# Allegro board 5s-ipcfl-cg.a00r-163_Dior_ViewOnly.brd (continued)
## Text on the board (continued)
TOP: list("[Spacing] TOP" "9.Shape to Route Keepout" "0 MIL [DEFAULT]" "0 MIL" "0.00 MIL" "DRC ERROR CLASS/TOP" "[Shape] Route Keepout/All ((-3363.8 -570.56) (-3302.8 -509.56))" "[Top Shape] +3P3V_MSATA ((-3456.02 -996.0) (-3345.0 1131.0))" list(-3355.620000 -560.850000) nil)@@@list("eric2_tseng" "2019/01/23 17:32:01" nil "p143000044-pc" "5s-ipcfl-cg.a00r")@@@list("doris_chen" "2019/01/24 12:51:12" nil "p16c000356-pc" "5s-ipcfl-cg.a00r-chk") | list("[Physical] TOP" "97.Pad/Pad Direct Connect" "NOT_ALLOWED [100OHM(DP_4/8/5/200)]" "ALL_ALLOWED" "" "DRC ERROR CLASS/TOP" "[SmdPin] LAN_MDI3_P_C (<uTiL>cId3603<uTiL>.1) (-3209.34 2359.74)" "[SmdPin] LAN_MDI3_P_C (<uTiL>cId3097<uTiL>.2) (-3209.32 2358.76)" list(-3209.320000 2358.760000) nil)@@@list("eric2_tseng" "2019/01/23 17:33:15" nil "p143000044-pc" "5s-ipcfl-cg.a00r")@@@list("doris_chen" "2019/01/24 12:52:08" nil "p16c000356-pc" "5s-ipcfl-cg.a00r-chk") | list("[Physical] TOP" "139.Pad/Pad Direct Connect" "NOT_ALLOWED [100OHM(DP_4/8/5/200)]" "ALL_ALLOWED" "" "DRC ERROR CLASS/TOP" "[SmdPin] LAN_MDI3_P (<uTiL>cId3097<uTiL>.1) (-3209.32 2293.8)" "[SmdPin] LAN_MDI3_P (<uTiL>cId3603<uTiL>.2) (-3209.3 2292.82)" list(-3209.300000 2292.820000) nil)@@@list("eric2_tseng" "2019/01/23 17:34:18" nil "p143000044-pc" "5s-ipcfl-cg.a00r")@@@list("doris_chen" "2019/01/24 12:52:31" nil "p16c000356-pc" "5s-ipcfl-cg.a00r-chk") | list("[Physical] TOP" "96.Pad/Pad Direct Connect" "NOT_ALLOWED [100OHM(DP_4/8/5/200)]" "ALL_ALLOWED" "" "DRC ERROR CLASS/TOP" "[SmdPin] LAN_MDI3_N (<uTiL>cId3097<uTiL>.3) (-3177.82 2293.8)" "[SmdPin] LAN_MDI3_N (<uTiL>cId3603<uTiL>.3) (-3177.84 2292.82)" list(-3177.840000 2292.820000) nil)@@@list("eric2_tseng" "2019/01/23 17:34:27" nil "p143000044-pc" "5s-ipcfl-cg.a00r")@@@list("doris_chen" "2019/01/24 12:52:07" nil "p16c000356-pc" "5s-ipcfl-cg.a00r-chk") | list("[Physical] TOP" "74.Pad/Pad Direct Connect" "NOT_ALLOWED [100OHM(DP_4/8/5/200)]" "ALL_ALLOWED" "" "DRC ERROR CLASS/TOP" "[SmdPin] LAN_MDI3_N_C (<uTiL>cId3603<uTiL>.4) (-3177.84 2359.74)" "[SmdPin] LAN_MDI3_N_C (<uTiL>cId3097<uTiL>.4) (-3177.82 2358.76)" list(-3177.820000 2358.760000) nil)@@@list("eric2_tseng" "2019/01/23 17:33:40" nil "p143000044-pc" "5s-ipcfl-cg.a00r")@@@list("doris_chen" "2019/01/24 12:51:55" nil "p16c000356-pc" "5s-ipcfl-cg.a00r-chk") | list("[Physical] TOP" "192.Pad/Pad Direct Connect" "NOT_ALLOWED [100OHM(DP_4/8/5/200)]" "ALL_ALLOWED" "" "DRC ERROR CLASS/TOP" "[SmdPin] LAN_MDI2_P_C (<uTiL>cId3602<uTiL>.1) (-3121.34 2383.74)" "[SmdPin] LAN_MDI2_P_C (<uTiL>cId3096<uTiL>.2) (-3121.32 2382.76)" list(-3121.320000 2382.760000) nil)@@@list("eric2_tseng" "2019/01/23 17:33:52" nil "p143000044-pc" "5s-ipcfl-cg.a00r")@@@list("doris_chen" "2019/01/24 12:53:02" nil "p16c000356-pc" "5s-ipcfl-cg.a00r-chk") | list("[Physical] TOP" "191.Pad/Pad Direct Connect" "NOT_ALLOWED [100OHM(DP_4/8/5/200)]" "ALL_ALLOWED" "" "DRC ERROR CLASS/TOP" "[SmdPin] LAN_MDI2_P (<uTiL>cId3096<uTiL>.1) (-3121.32 2317.8)" "[SmdPin] LAN_MDI2_P (<uTiL>cId3602<uTiL>.2) (-3121.3 2316.82)" list(-3121.300000 2316.820000) nil)@@@list("eric2_tseng" "2019/01/23 17:33:17" nil "p143000044-pc" "5s-ipcfl-cg.a00r")@@@list("doris_chen" "2019/01/24 12:53:01" nil "p16c000356-pc" "5s-ipcfl-cg.a00r-chk") | list("[Physical] TOP" "75.Pad/Pad Direct Connect" "NOT_ALLOWED [100OHM(DP_4/8/5/200)]" "ALL_ALLOWED" "" "DRC ERROR CLASS/TOP" "[SmdPin] LAN_MDI2_N_C (<uTiL>cId3096<uTiL>.4) (-3089.82 2382.76)" "[SmdPin] LAN_MDI2_N_C (<uTiL>cId3602<uTiL>.4) (-3089.84 2383.74)" list(-3089.840000 2383.740000) nil)@@@list("eric2_tseng" "2019/01/23 17:33:46" nil "p143000044-pc" "5s-ipcfl-cg.a00r")@@@list("doris_chen" "2019/01/24 12:51:56" nil "p16c000356-pc" "5s-ipcfl-cg.a00r-chk") | list("[Physical] TOP" "104.Pad/Pad Direct Connect" "NOT_ALLOWED [100OHM(DP_4/8/5/200)]" "ALL_ALLOWED" "" "DRC ERROR CLASS/TOP" "[SmdPin] LAN_MDI2_N (<uTiL>cId3602<uTiL>.3) (-3089.84 2316.82)" "[SmdPin] LAN_MDI2_N (<uTiL>cId3096<uTiL>.3) (-3089.82 2317.8)" list(-3089.820000 2317.800000) nil)@@@list("eric2_tseng" "2019/01/23 17:33:16" nil "p143000044-pc" "5s-ipcfl-cg.a00r")@@@list("doris_chen" "2019/01/24 12:52:12" nil "p16c000356-pc" "5s-ipcfl-cg.a00r-chk") | list("[Physical] TOP" "141.Pad/Pad Direct Connect" "NOT_ALLOWED [100OHM(DP_4/8/5/200)]" "ALL_ALLOWED" "" "DRC ERROR CLASS/TOP" "[SmdPin] LAN_MDI1_P_C (<uTiL>cId3095<uTiL>.2) (-3033.32 2382.76)" "[SmdPin] LAN_MDI1_P_C (<uTiL>cId3601<uTiL>.1) (-3033.34 2383.74)" list(-3033.340000 2383.740000) nil)@@@list("eric2_tseng" "2019/01/23 17:34:15" nil "p143000044-pc" "5s-ipcfl-cg.a00r")@@@list("doris_chen" "2019/01/24 12:52:32" nil "p16c000356-pc" "5s-ipcfl-cg.a00r-chk") | list("[Physical] TOP" "140.Pad/Pad Direct Connect" "NOT_ALLOWED [100OHM(DP_4/8/5/200)]" "ALL_ALLOWED" "" "DRC ERROR CLASS/TOP" "[SmdPin] LAN_MDI1_P (<uTiL>cId3095<uTiL>.1) (-3033.32 2317.8)" "[SmdPin] LAN_MDI1_P (<uTiL>cId3601<uTiL>.2) (-3033.3 2316.82)" list(-3033.300000 2316.820000) nil)@@@list("eric2_tseng" "2019/01/23 17:33:57" nil "p143000044-pc" "5s-ipcfl-cg.a00r")@@@list("doris_chen" "2019/01/24 12:52:31" nil "p16c000356-pc" "5s-ipcfl-cg.a00r-chk") | list("[Physical] TOP" "99.Pad/Pad Direct Connect" "NOT_ALLOWED [100OHM(DP_4/8/5/200)]" "ALL_ALLOWED" "" "DRC ERROR CLASS/TOP" "[SmdPin] LAN_MDI1_N_C (<uTiL>cId3095<uTiL>.4) (-3001.82 2382.76)" "[SmdPin] LAN_MDI1_N_C (<uTiL>cId3601<uTiL>.4) (-3001.84 2383.74)" list(-3001.840000 2383.740000) nil)@@@list("eric2_tseng" "2019/01/23 17:34:14" nil "p143000044-pc" "5s-ipcfl-cg.a00r")@@@list("doris_chen" "2019/01/24 12:52:09" nil "p16c000356-pc" "5s-ipcfl-cg.a00r-chk") | list("[Physical] TOP" "98.Pad/Pad Direct Connect" "NOT_ALLOWED [100OHM(DP_4/8/5/200)]" "ALL_ALLOWED" "" "DRC ERROR CLASS/TOP" "[SmdPin] LAN_MDI1_N (<uTiL>cId3095<uTiL>.3) (-3001.82 2317.8)" "[SmdPin] LAN_MDI1_N (<uTiL>cId3601<uTiL>.3) (-3001.84 2316.82)" list(-3001.840000 2316.820000) nil)@@@list("eric2_tseng" "2019/01/23 17:33:16" nil "p143000044-pc" "5s-ipcfl-cg.a00r")@@@list("doris_chen" "2019/01/24 12:52:08" nil "p16c000356-pc" "5s-ipcfl-cg.a00r-chk") | list("[Physical] TOP" "45.Pad/Pad Direct Connect" "NOT_ALLOWED [100OHM(DP_4/8/5/200)]" "ALL_ALLOWED" "" "DRC ERROR CLASS/TOP" "[SmdPin] LAN_MDI0_P_C (<uTiL>cId3600<uTiL>.1) (-2944.34 2383.74)" "[SmdPin] LAN_MDI0_P_C (<uTiL>cId3094<uTiL>.2) (-2944.32 2382.76)" list(-2944.320000 2382.760000) nil)@@@list("eric2_tseng" "2019/01/23 17:33:46" nil "p143000044-pc" "5s-ipcfl-cg.a00r")@@@list("doris_chen" "2019/01/24 12:51:36" nil "p16c000356-pc" "5s-ipcfl-cg.a00r-chk") | list("[Physical] TOP" "193.Pad/Pad Direct Connect" "NOT_ALLOWED [100OHM(DP_4/8/5/200)]" "ALL_ALLOWED" "" "DRC ERROR CLASS/TOP" "[SmdPin] LAN_MDI0_P (<uTiL>cId3600<uTiL>.2) (-2944.3 2316.82)" "[SmdPin] LAN_MDI0_P (<uTiL>cId3094<uTiL>.1) (-2944.32 2317.8)" list(-2944.320000 2317.800000) nil)@@@list("eric2_tseng" "2019/01/23 17:33:17" nil "p143000044-pc" "5s-ipcfl-cg.a00r")@@@list("doris_chen" "2019/01/24 12:53:02" nil "p16c000356-pc" "5s-ipcfl-cg.a00r-chk") | list("[Physical] TOP" "86.Pad/Pad Direct Connect" "NOT_ALLOWED [100OHM(DP_4/8/5/200)]" "ALL_ALLOWED" "" "DRC ERROR CLASS/TOP" "[SmdPin] LAN_MDI0_N_C (<uTiL>cId3094<uTiL>.4) (-2912.82 2382.76)" "[SmdPin] LAN_MDI0_N_C (<uTiL>cId3600<uTiL>.4) (-2912.84 2383.74)" list(-2912.840000 2383.740000) nil)@@@list("eric2_tseng" "2019/01/23 17:33:58" nil "p143000044-pc" "5s-ipcfl-cg.a00r")@@@list("doris_chen" "2019/01/24 12:52:02" nil "p16c000356-pc" "5s-ipcfl-cg.a00r-chk") | list("[Physical] TOP" "76.Pad/Pad Direct Connect" "NOT_ALLOWED [100OHM(DP_4/8/5/200)]" "ALL_ALLOWED" "" "DRC ERROR CLASS/TOP" "[SmdPin] LAN_MDI0_N (<uTiL>cId3600<uTiL>.3) (-2912.84 2316.82)" "[SmdPin] LAN_MDI0_N (<uTiL>cId3094<uTiL>.3) (-2912.82 2317.8)" list(-2912.820000 2317.800000) nil)@@@list("eric2_tseng" "2019/01/23 17:34:28" nil "p143000044-pc" "5s-ipcfl-cg.a00r")@@@list("doris_chen" "2019/01/24 12:51:56" nil "p16c000356-pc" "5s-ipcfl-cg.a00r-chk") | list("[Physical] TOP" "169.Pad/Pad Direct Connect" "NOT_ALLOWED [(GND_20)]" "ALL_ALLOWED" "" "DRC ERROR CLASS/TOP" "[ThruPin] GND (<uTiL>cId2106<uTiL>.52) (-2879.07 -1710.4)" "[SmdPin] GND (<uTiL>cId2106<uTiL>.49) (-2799.57 -1789.9)" list(-2879.070000 -1710.400000) nil)@@@list("eric2_tseng" "2019/01/23 17:33:20" nil "p143000044-pc" "5s-ipcfl-cg.a00r")@@@list("doris_chen" "2019/01/24 12:52:50" nil "p16c000356-pc" "5s-ipcfl-cg.a00r-chk") | list("[Physical] TOP" "170.Pad/Pad Direct Connect" "NOT_ALLOWED [(GND_20)]" "ALL_ALLOWED" "" "DRC ERROR CLASS/TOP" "[ThruPin] GND (<uTiL>cId2106<uTiL>.54) (-2879.07 -1789.9)" "[SmdPin] GND (<uTiL>cId2106<uTiL>.49) (-2799.57 -1789.9)" list(-2879.070000 -1789.900000) nil)@@@list("eric2_tseng" "2019/01/23 17:34:10" nil "p143000044-pc" "5s-ipcfl-cg.a00r")@@@list("doris_chen" "2019/01/24 12:52:50" nil "p16c000356-pc" "5s-ipcfl-cg.a00r-chk") | list("[Physical] TOP" "172.Pad/Pad Direct Connect" "NOT_ALLOWED [(GND_20)]" "ALL_ALLOWED" "" "DRC ERROR CLASS/TOP" "[ThruPin] GND (<uTiL>cId2106<uTiL>.57) (-2879.07 -1869.4)" "[SmdPin] GND (<uTiL>cId2106<uTiL>.49) (-2799.57 -1789.9)" list(-2879.070000 -1869.400000) nil)@@@list("eric2_tseng" "2019/01/23 17:33:59" nil "p143000044-pc" "5s-ipcfl-cg.a00r")@@@list("doris_chen" "2019/01/24 12:52:51" nil "p16c000356-pc" "5s-ipcfl-cg.a00r-chk") | list("[Physical] TOP" "168.Pad/Pad Direct Connect" "NOT_ALLOWED [(GND_20)]" "ALL_ALLOWED" "" "DRC ERROR CLASS/TOP" "[ThruPin] GND (<uTiL>cId2106<uTiL>.51) (-2799.57 -1710.4)" "[SmdPin] GND (<uTiL>cId2106<uTiL>.49) (-2799.57 -1789.9)" list(-2799.570000 -1710.400000) nil)@@@list("eric2_tseng" "2019/01/23 17:33:21" nil "p143000044-pc" "5s-ipcfl-cg.a00r")@@@list("doris_chen" "2019/01/24 12:52:49" nil "p16c000356-pc" "5s-ipcfl-cg.a00r-chk") | list("[Physical] TOP" "173.Pad/Pad Direct Connect" "NOT_ALLOWED [(GND_20)]" "ALL_ALLOWED" "" "DRC ERROR CLASS/TOP" "[ThruPin] GND (<uTiL>cId2106<uTiL>.58) (-2799.57 -1789.9)" "[SmdPin] GND (<uTiL>cId2106<uTiL>.49) (-2799.57 -1789.9)" list(-2799.570000 -1789.900000) nil)@@@list("eric2_tseng" "2019/01/23 17:33:19" nil "p143000044-pc" "5s-ipcfl-cg.a00r")@@@list("doris_chen" "2019/01/24 12:52:52" nil "p16c000356-pc" "5s-ipcfl-cg.a00r-chk") | list("[Physical] TOP" "171.Pad/Pad Direct Connect" "NOT_ALLOWED [(GND_20)]" "ALL_ALLOWED" "" "DRC ERROR CLASS/TOP" "[ThruPin] GND (<uTiL>cId2106<uTiL>.56) (-2799.57 -1869.4)" "[SmdPin] GND (<uTiL>cId2106<uTiL>.49) (-2799.57 -1789.9)" list(-2799.570000 -1869.400000) nil)@@@list("eric2_tseng" "2019/01/23 17:33:20" nil "p143000044-pc" "5s-ipcfl-cg.a00r")@@@list("doris_chen" "2019/01/24 12:52:51" nil "p16c000356-pc" "5s-ipcfl-cg.a00r-chk") | list("[Spacing] TOP" "14.Shape to Route Keepin" "0 MIL [DEFAULT]" "0 MIL" "0.00 MIL" "DRC ERROR CLASS/TOP" "[Shape] Route Keepin/All ((-3483.94 -2629.6) (3168.97 4113.86))" "[Top Shape] GND ((-2728.18 -2401.25) (-2614.45 -2216.13))" list(-2728.030000 -2224.450000) nil)@@@list("eric2_tseng" "2019/01/23 17:32:01" nil "p143000044-pc" "5s-ipcfl-cg.a00r")@@@list("doris_chen" "2019/01/24 12:51:15" nil "p16c000356-pc" "5s-ipcfl-cg.a00r-chk") | list("[Physical] TOP" "166.Pad/Pad Direct Connect" "NOT_ALLOWED [(GND_20)]" "ALL_ALLOWED" "" "DRC ERROR CLASS/TOP" "[ThruPin] GND (<uTiL>cId2106<uTiL>.50) (-2720.07 -1710.4)" "[SmdPin] GND (<uTiL>cId2106<uTiL>.49) (-2799.57 -1789.9)" list(-2720.070000 -1710.400000) nil)@@@list("eric2_tseng" "2019/01/23 17:33:21" nil "p143000044-pc" "5s-ipcfl-cg.a00r")@@@list("doris_chen" "2019/01/24 12:52:48" nil "p16c000356-pc" "5s-ipcfl-cg.a00r-chk") | list("[Physical] TOP" "174.Pad/Pad Direct Connect" "NOT_ALLOWED [(GND_20)]" "ALL_ALLOWED" "" "DRC ERROR CLASS/TOP" "[SmdPin] GND (<uTiL>cId2106<uTiL>.49) (-2799.57 -1789.9)" "[ThruPin] GND (<uTiL>cId2106<uTiL>.53) (-2720.07 -1789.9)" list(-2720.070000 -1789.900000) nil)@@@list("eric2_tseng" "2019/01/23 17:33:42" nil "p143000044-pc" "5s-ipcfl-cg.a00r")@@@list("doris_chen" "2019/01/24 12:52:52" nil "p16c000356-pc" "5s-ipcfl-cg.a00r-chk") | list("[Physical] TOP" "167.Pad/Pad Direct Connect" "NOT_ALLOWED [(GND_20)]" "ALL_ALLOWED" "" "DRC ERROR CLASS/TOP" "[ThruPin] GND (<uTiL>cId2106<uTiL>.55) (-2720.07 -1869.4)" "[SmdPin] GND (<uTiL>cId2106<uTiL>.49) (-2799.57 -1789.9)" list(-2720.070000 -1869.400000) nil)@@@list("eric2_tseng" "2019/01/23 17:34:21" nil "p143000044-pc" "5s-ipcfl-cg.a00r")@@@list("doris_chen" "2019/01/24 12:52:49" nil "p16c000356-pc" "5s-ipcfl-cg.a00r-chk") | list("[Physical] TOP" "161.Pad/Pad Direct Connect" "NOT_ALLOWED [(PWR_20)]" "ALL_ALLOWED" "" "DRC ERROR CLASS/TOP" "[SmdPin] +VCCSA_VIN (<uTiL>cId5471<uTiL>.1) (-2412.4 1987.1)" "[SmdPin] +VCCSA_VIN (<uTiL>cId5435<uTiL>.2) (-2412.0 2000.5)" list(-2412.000000 2000.500000) nil)@@@list("eric2_tseng" "2019/01/23 17:34:21" nil "p143000044-pc" "5s-ipcfl-cg.a00r")@@@list("doris_chen" "2019/01/24 12:52:45" nil "p16c000356-pc" "5s-ipcfl-cg.a00r-chk") | list("[Spacing] TOP" "1.Shape to Route Keepin" "0 MIL [DEFAULT]" "0 MIL" "0.00 MIL" "DRC ERROR CLASS/TOP" "[Shape] Route Keepin/All ((-3483.94 -2629.6) (3168.97 4113.86))" "[Top Shape] GND_AUDIO ((-2594.47 -2629.61) (-2177.88 -2145.28))" list(-2379.690000 -2629.600000) nil)@@@list("eric2_tseng" "2019/01/23 17:31:58" nil "p143000044-pc" "5s-ipcfl-cg.a00r")@@@list("doris_chen" "2019/01/24 12:51:08" nil "p16c000356-pc" "5s-ipcfl-cg.a00r-chk") | list("[Physical] TOP" "91.Pad/Pad Direct Connect" "NOT_ALLOWED [85OHM(DP_5|5/5|5.5/5/200)]" "ALL_ALLOWED" "" "DRC ERROR CLASS/TOP" "[SmdPin] USB_PP14_M.2_BT_R (<uTiL>cId3099<uTiL>.2) (-2302.18 -421.8)" "[SmdPin] USB_PP14_M.2_BT_R (<uTiL>cId3180<uTiL>.3) (-2302.18 -417.86)" list(-2302.180000 -417.860000) nil)@@@list("eric2_tseng" "2019/01/23 17:33:44" nil "p143000044-pc" "5s-ipcfl-cg.a00r")@@@list("doris_chen" "2019/01/24 12:52:05" nil "p16c000356-pc" "5s-ipcfl-cg.a00r-chk") | list("[Physical] TOP" "135.Pad/Pad Direct Connect" "NOT_ALLOWED [85OHM(DP_5|5/5|5.5/5/200)]" "ALL_ALLOWED" "" "DRC ERROR CLASS/TOP" "[SmdPin] USB_PP14_M.2_BT (<uTiL>cId3180<uTiL>.4) (-2302.18 -490.7)" "[SmdPin] USB_PP14_M.2_BT (<uTiL>cId3099<uTiL>.1) (-2302.18 -486.76)" list(-2302.180000 -486.760000) nil)@@@list("eric2_tseng" "2019/01/23 17:34:25" nil "p143000044-pc" "5s-ipcfl-cg.a00r")@@@list("doris_chen" "2019/01/24 12:52:28" nil "p16c000356-pc" "5s-ipcfl-cg.a00r-chk") | list("[Physical] TOP" "190.Pad/Pad Direct Connect" "NOT_ALLOWED [85OHM(DP_5|5/5|5.5/5/200)]" "ALL_ALLOWED" "" "DRC ERROR CLASS/TOP" "[SmdPin] USB_PN14_M.2_BT_R (<uTiL>cId3180<uTiL>.2) (-2270.68 -417.86)" "[SmdPin] USB_PN14_M.2_BT_R (<uTiL>cId3099<uTiL>.4) (-2270.68 -421.8)" list(-2270.680000 -421.800000) nil)@@@list("eric2_tseng" "2019/01/23 17:34:20" nil "p143000044-pc" "5s-ipcfl-cg.a00r")@@@list("doris_chen" "2019/01/24 12:53:01" nil "p16c000356-pc" "5s-ipcfl-cg.a00r-chk") | list("[Physical] TOP" "103.Pad/Pad Direct Connect" "NOT_ALLOWED [85OHM(DP_5|5/5|5.5/5/200)]" "ALL_ALLOWED" "" "DRC ERROR CLASS/TOP" "[SmdPin] USB_PN14_M.2_BT (<uTiL>cId3180<uTiL>.1) (-2270.68 -490.7)" "[SmdPin] USB_PN14_M.2_BT (<uTiL>cId3099<uTiL>.3) (-2270.68 -486.76)" list(-2270.680000 -486.760000) nil)@@@list("eric2_tseng" "2019/01/23 17:33:11" nil "p143000044-pc" "5s-ipcfl-cg.a00r")@@@list("doris_chen" "2019/01/24 12:52:11" nil "p16c000356-pc" "5s-ipcfl-cg.a00r-chk") | list("[Physical] TOP" "142.Pad/Pad Direct Connect" "NOT_ALLOWED [DEFAULT]" "ALL_ALLOWED" "" "DRC ERROR CLASS/TOP" "[ThruPin] PCH_HEATSINK_DET (<uTiL>cId6011<uTiL>.4) (-2152.51 -10.63)" "[ThruPin] PCH_HEATSINK_DET (<uTiL>cId5725<uTiL>.1) (-2152.52 -10.63)" list(-2152.520000 -10.630000) nil)@@@list("eric2_tseng" "2019/01/23 17:34:16" nil "p143000044-pc" "5s-ipcfl-cg.a00r")@@@list("doris_chen" "2019/01/24 12:52:32" nil "p16c000356-pc" "5s-ipcfl-cg.a00r-chk") | list("[Spacing-SameNet] TOP" "36.Line to Line Same Net" "4 MIL [DEFAULT]" "0 MIL" "4.00 MIL" "DRC ERROR CLASS/TOP" "[Line] PCH_HEATSINK_DET ((-2154.52 -68.02) (-2150.52 -8.63))" "[Line] PCH_HEATSINK_DET ((-2154.51 -12.63) (-2150.51 -8.62))" list(-2152.520000 -10.630000) nil)@@@list("eric2_tseng" "2019/01/23 17:32:53" nil "p143000044-pc" "5s-ipcfl-cg.a00r")@@@list("doris_chen" "2019/01/24 12:51:32" nil "p16c000356-pc" "5s-ipcfl-cg.a00r-chk") | list("[Physical] TOP" "109.Pad/Pad Direct Connect" "NOT_ALLOWED [DEFAULT]" "ALL_ALLOWED" "" "DRC ERROR CLASS/TOP" "[ThruPin] PCH_HEATSINK_DET (<uTiL>cId5725<uTiL>.2) (-2152.52 189.37)" "[ThruPin] PCH_HEATSINK_DET (<uTiL>cId6011<uTiL>.3) (-2152.51 189.37)" list(-2152.510000 189.370000) nil)@@@list("eric2_tseng" "2019/01/23 17:34:16" nil "p143000044-pc" "5s-ipcfl-cg.a00r")@@@list("doris_chen" "2019/01/24 12:52:14" nil "p16c000356-pc" "5s-ipcfl-cg.a00r-chk") | list("[Physical] TOP" "159.Pad/Pad Direct Connect" "NOT_ALLOWED [85OHM(DP_5|5/5|5.5/5/200)]" "ALL_ALLOWED" "" "DRC ERROR CLASS/TOP" "[SmdPin] USB_PP7_B3_R (<uTiL>cId698<uTiL>.4) (-1911.55 3427.18)" "[SmdPin] USB_PP7_B3_R (<uTiL>cId634<uTiL>.2) (-1913.52 3425.21)" list(-1913.520000 3425.210000) nil)@@@list("eric2_tseng" "2019/01/23 17:33:44" nil "p143000044-pc" "5s-ipcfl-cg.a00r")@@@list("doris_chen" "2019/01/24 12:52:44" nil "p16c000356-pc" "5s-ipcfl-cg.a00r-chk") | list("[Physical] TOP" "72.Pad/Pad Direct Connect" "NOT_ALLOWED [85OHM(DP_5|5/5|5.5/5/200)]" "ALL_ALLOWED" "" "DRC ERROR CLASS/TOP" "[SmdPin] USB_PP7_B3 (<uTiL>cId634<uTiL>.1) (-1913.52 3379.93)" "[SmdPin] USB_PP7_B3 (<uTiL>cId698<uTiL>.1) (-1911.55 3377.96)" list(-1911.550000 3377.960000) nil)@@@list("eric2_tseng" "2019/01/23 17:34:24" nil "p143000044-pc" "5s-ipcfl-cg.a00r")@@@list("doris_chen" "2019/01/24 12:51:54" nil "p16c000356-pc" "5s-ipcfl-cg.a00r-chk") | list("[Physical] TOP" "59.Pad/Pad Direct Connect" "NOT_ALLOWED [85OHM(DP_5|5/5|5.5/5/200)]" "ALL_ALLOWED" "" "DRC ERROR CLASS/TOP" "[SmdPin] USB_PN7_B3_R (<uTiL>cId634<uTiL>.4) (-1887.92 3425.21)" "[SmdPin] USB_PN7_B3_R (<uTiL>cId698<uTiL>.3) (-1889.89 3427.18)" list(-1889.890000 3427.180000) nil)@@@list("eric2_tseng" "2019/01/23 17:33:41" nil "p143000044-pc" "5s-ipcfl-cg.a00r")@@@list("doris_chen" "2019/01/24 12:51:44" nil "p16c000356-pc" "5s-ipcfl-cg.a00r-chk") | list("[Physical] TOP" "188.Pad/Pad Direct Connect" "NOT_ALLOWED [85OHM(DP_5|5/5|5.5/5/200)]" "ALL_ALLOWED" "" "DRC ERROR CLASS/TOP" "[SmdPin] USB_PN7_B3 (<uTiL>cId634<uTiL>.3) (-1887.92 3379.93)" "[SmdPin] USB_PN7_B3 (<uTiL>cId698<uTiL>.2) (-1889.89 3377.96)" list(-1889.890000 3377.960000) nil)@@@list("eric2_tseng" "2019/01/23 17:33:09" nil "p143000044-pc" "5s-ipcfl-cg.a00r")@@@list("doris_chen" "2019/01/24 12:53:00" nil "p16c000356-pc" "5s-ipcfl-cg.a00r-chk") | list("[Physical] TOP" "120.Pad/Pad Direct Connect" "NOT_ALLOWED [85OHM(DP_5|5/5|5.5/5/200)]" "ALL_ALLOWED" "" "DRC ERROR CLASS/TOP" "[SmdPin] USB_PP8_B4 (<uTiL>cId697<uTiL>.1) (-1851.55 3377.96)" "[SmdPin] USB_PP8_B4 (<uTiL>cId631<uTiL>.1) (-1853.52 3379.93)" list(-1853.520000 3379.930000) nil)@@@list("eric2_tseng" "2019/01/23 17:33:13" nil "p143000044-pc" "5s-ipcfl-cg.a00r")@@@list("doris_chen" "2019/01/24 12:52:21" nil "p16c000356-pc" "5s-ipcfl-cg.a00r-chk") | list("[Physical] TOP" "187.Pad/Pad Direct Connect" "NOT_ALLOWED [85OHM(DP_5|5/5|5.5/5/200)]" "ALL_ALLOWED" "" "DRC ERROR CLASS/TOP" "[SmdPin] USB_PP8_B4_R (<uTiL>cId631<uTiL>.2) (-1853.52 3425.21)" "[SmdPin] USB_PP8_B4_R (<uTiL>cId697<uTiL>.4) (-1851.55 3427.18)" list(-1851.550000 3427.180000) nil)@@@list("eric2_tseng" "2019/01/23 17:34:24" nil "p143000044-pc" "5s-ipcfl-cg.a00r")@@@list("doris_chen" "2019/01/24 12:52:59" nil "p16c000356-pc" "5s-ipcfl-cg.a00r-chk") | list("[Physical] TOP" "94.Pad/Pad Direct Connect" "NOT_ALLOWED [85OHM(DP_5|5/5|5.5/5/200)]" "ALL_ALLOWED" "" "DRC ERROR CLASS/TOP" "[SmdPin] USB_PN8_B4_R (<uTiL>cId631<uTiL>.4) (-1827.92 3425.21)" "[SmdPin] USB_PN8_B4_R (<uTiL>cId697<uTiL>.3) (-1829.89 3427.18)" list(-1829.890000 3427.180000) nil)@@@list("eric2_tseng" "2019/01/23 17:34:23" nil "p143000044-pc" "5s-ipcfl-cg.a00r")@@@list("doris_chen" "2019/01/24 12:52:06" nil "p16c000356-pc" "5s-ipcfl-cg.a00r-chk") | list("[Physical] TOP" "87.Pad/Pad Direct Connect" "NOT_ALLOWED [85OHM(DP_5|5/5|5.5/5/200)]" "ALL_ALLOWED" "" "DRC ERROR CLASS/TOP" "[SmdPin] USB_PN8_B4 (<uTiL>cId697<uTiL>.2) (-1829.89 3377.96)" "[SmdPin] USB_PN8_B4 (<uTiL>cId631<uTiL>.3) (-1827.92 3379.93)" list(-1827.920000 3379.930000) nil)@@@list("eric2_tseng" "2019/01/23 17:33:11" nil "p143000044-pc" "5s-ipcfl-cg.a00r")@@@list("doris_chen" "2019/01/24 12:52:02" nil "p16c000356-pc" "5s-ipcfl-cg.a00r-chk") | list("[Spacing] TOP" "12.Shape to Route Keepin" "0 MIL [DEFAULT]" "0 MIL" "0.00 MIL" "DRC ERROR CLASS/TOP" "[Shape] Route Keepin/All ((-3483.94 -2629.6) (3168.97 4113.86))" "[Top Shape] GND_AUDIO ((-2170.95 -2629.61) (-1679.58 -2154.72))" list(-1679.580000 -2629.600000) nil)@@@list("eric2_tseng" "2019/01/23 17:32:00" nil "p143000044-pc" "5s-ipcfl-cg.a00r")@@@list("doris_chen" "2019/01/24 12:51:14" nil "p16c000356-pc" "5s-ipcfl-cg.a00r-chk") | list("[Spacing] TOP" "13.Shape to Route Keepin" "0 MIL [DEFAULT]" "0 MIL" "0.00 MIL" "DRC ERROR CLASS/TOP" "[Shape] Route Keepin/All ((-3483.94 -2629.6) (3168.97 4113.86))" "[Top Shape] GND ((-1658.98 -2629.61) (-868.57 -2250.87))" list(-1658.980000 -2629.600000) nil)@@@list("eric2_tseng" "2019/01/23 17:31:59" nil "p143000044-pc" "5s-ipcfl-cg.a00r")@@@list("doris_chen" "2019/01/24 12:51:14" nil "p16c000356-pc" "5s-ipcfl-cg.a00r-chk") | list("[Physical] TOP" "65.Pad/Pad Direct Connect" "NOT_ALLOWED [(GND_20)]" "ALL_ALLOWED" "" "DRC ERROR CLASS/TOP" "[SmdPin] GND (<uTiL>cId5666<uTiL>.17) (-1505.0 2702.0)" "[ThruPin] GND (<uTiL>cId5666<uTiL>.18) (-1526.0 2723.0)" list(-1526.000000 2723.000000) nil)@@@list("eric2_tseng" "2019/01/23 17:33:22" nil "p143000044-pc" "5s-ipcfl-cg.a00r")@@@list("doris_chen" "2019/01/24 12:51:50" nil "p16c000356-pc" "5s-ipcfl-cg.a00r-chk") | list("[Spacing] TOP" "7.SMD Pin to SMD Pin" "5 MIL [DEFAULT]" "OVERLAP" "" "DRC ERROR CLASS/TOP" "[SmdPin] Dummy (<uTiL>cId5785<uTiL>.3) (-1471.26 213.0)" "[SmdPin] Dummy (<uTiL>cId4553<uTiL>.3) (-1470.98 213.0)" list(-1500.480000 203.000000) nil)@@@list("eric2_tseng" "2019/01/23 17:31:57" nil "p143000044-pc" "5s-ipcfl-cg.a00r")@@@list("doris_chen" "2019/01/24 12:51:11" nil "p16c000356-pc" "5s-ipcfl-cg.a00r-chk") | list("[Spacing] TOP" "11.SMD Pin to SMD Pin" "5 MIL [DEFAULT]" "OVERLAP" "" "DRC ERROR CLASS/TOP" "[SmdPin] Dummy (<uTiL>cId5785<uTiL>.4) (-1471.26 163.0)" "[SmdPin] Dummy (<uTiL>cId4553<uTiL>.4) (-1470.98 163.0)" list(-1500.480000 153.000000) nil)@@@list("eric2_tseng" "2019/01/23 17:31:58" nil "p143000044-pc" "5s-ipcfl-cg.a00r")@@@list("doris_chen" "2019/01/24 12:51:13" nil "p16c000356-pc" "5s-ipcfl-cg.a00r-chk") | list("[Spacing] TOP" "4.SMD Pin to SMD Pin" "5 MIL [DEFAULT]" "OVERLAP" "" "DRC ERROR CLASS/TOP" "[SmdPin] Dummy (<uTiL>cId5785<uTiL>.5) (-1471.26 113.0)" "[SmdPin] Dummy (<uTiL>cId4553<uTiL>.5) (-1470.98 113.0)" list(-1500.480000 103.000000) nil)@@@list("eric2_tseng" "2019/01/23 17:32:00" nil "p143000044-pc" "5s-ipcfl-cg.a00r")@@@list("doris_chen" "2019/01/24 12:51:10" nil "p16c000356-pc" "5s-ipcfl-cg.a00r-chk") | list("[Spacing] TOP" "15.SMD Pin to SMD Pin" "5 MIL [DEFAULT]" "OVERLAP" "" "DRC ERROR CLASS/TOP" "[SmdPin] Dummy (<uTiL>cId5785<uTiL>.6) (-1471.26 63.0)" "[SmdPin] Dummy (<uTiL>cId4553<uTiL>.6) (-1470.98 63.0)" list(-1500.480000 53.000000) nil)@@@list("eric2_tseng" "2019/01/23 17:31:58" nil "p143000044-pc" "5s-ipcfl-cg.a00r")@@@list("doris_chen" "2019/01/24 12:51:15" nil "p16c000356-pc" "5s-ipcfl-cg.a00r-chk") | list("[Physical] TOP" "164.Pad/Pad Direct Connect" "NOT_ALLOWED [(GND_20)]" "ALL_ALLOWED" "" "DRC ERROR CLASS/TOP" "[SmdPin] GND (<uTiL>cId5666<uTiL>.17) (-1505.0 2702.0)" "[ThruPin] GND (<uTiL>cId5666<uTiL>.19) (-1484.0 2681.0)" list(-1484.000000 2681.000000) nil)@@@list("eric2_tseng" "2019/01/23 17:34:10" nil "p143000044-pc" "5s-ipcfl-cg.a00r")@@@list("doris_chen" "2019/01/24 12:52:47" nil "p16c000356-pc" "5s-ipcfl-cg.a00r-chk") | list("[Physical] TOP" "95.Pad/Pad Direct Connect" "NOT_ALLOWED [50OHM(5)]" "ALL_ALLOWED" "" "DRC ERROR CLASS/TOP" "[SmdPin] R_SPI_IO3_R (<uTiL>cId5785<uTiL>.1) (-1471.26 313.0)" "[SmdPin] R_SPI_IO3_R (<uTiL>cId4553<uTiL>.1) (-1470.98 313.0)" list(-1470.980000 313.000000) nil)@@@list("eric2_tseng" "2019/01/23 17:33:45" nil "p143000044-pc" "5s-ipcfl-cg.a00r")@@@list("doris_chen" "2019/01/24 12:52:07" nil "p16c000356-pc" "5s-ipcfl-cg.a00r-chk") | list("[Physical] TOP" "100.Pad/Pad Direct Connect" "NOT_ALLOWED [(PWR_20)]" "ALL_ALLOWED" "" "DRC ERROR CLASS/TOP" "[SmdPin] +3P3VSB (<uTiL>cId5785<uTiL>.2) (-1471.26 263.0)" "[SmdPin] +3P3VSB (<uTiL>cId4553<uTiL>.2) (-1470.98 263.0)" list(-1470.980000 263.000000) nil)@@@list("eric2_tseng" "2019/01/23 17:33:28" nil "p143000044-pc" "5s-ipcfl-cg.a00r")@@@list("doris_chen" "2019/01/24 12:52:09" nil "p16c000356-pc" "5s-ipcfl-cg.a00r-chk") | list("[Physical] TOP" "110.Pad/Pad Direct Connect" "NOT_ALLOWED [50OHM(5)]" "ALL_ALLOWED" "" "DRC ERROR CLASS/TOP" "[SmdPin] R_SPI_CS0#_E56 (<uTiL>cId5785<uTiL>.7) (-1471.26 13.0)" "[SmdPin] R_SPI_CS0#_E56 (<uTiL>cId4553<uTiL>.7) (-1470.98 13.0)" list(-1470.980000 13.000000) nil)@@@list("eric2_tseng" "2019/01/23 17:33:12" nil "p143000044-pc" "5s-ipcfl-cg.a00r")@@@list("doris_chen" "2019/01/24 12:52:15" nil "p16c000356-pc" "5s-ipcfl-cg.a00r-chk") | list("[Physical] TOP" "189.Pad/Pad Direct Connect" "NOT_ALLOWED [50OHM(5)]" "ALL_ALLOWED" "" "DRC ERROR CLASS/TOP" "[SmdPin] R_SPI_IO1 (<uTiL>cId5785<uTiL>.8) (-1471.26 -37.0)" "[SmdPin] R_SPI_IO1 (<uTiL>cId4553<uTiL>.8) (-1470.98 -37.0)" list(-1470.980000 -37.000000) nil)@@@list("eric2_tseng" "2019/01/23 17:34:07" nil "p143000044-pc" "5s-ipcfl-cg.a00r")@@@list("doris_chen" "2019/01/24 12:53:00" nil "p16c000356-pc" "5s-ipcfl-cg.a00r-chk") | list("[Physical] TOP" "176.Pad/Pad Direct Connect" "NOT_ALLOWED [(PWR_20)]" "ALL_ALLOWED" "" "DRC ERROR CLASS/TOP" "[SmdPin] +VCCSA (<uTiL>cId5433<uTiL>.1) (-1242.99 1900.49)" "[SmdPin] +VCCSA (<uTiL>cId5656<uTiL>.1) (-1243.7 1841.92)" list(-1242.990000 1900.490000) nil)@@@list("eric2_tseng" "2019/01/23 17:34:11" nil "p143000044-pc" "5s-ipcfl-cg.a00r")@@@list("doris_chen" "2019/01/24 12:52:53" nil "p16c000356-pc" "5s-ipcfl-cg.a00r-chk") | list("[Spacing] TOP" "6.SMD Pin to SMD Pin" "5 MIL [DEFAULT]" "OVERLAP" "" "DRC ERROR CLASS/TOP" "[SmdPin] Dummy (<uTiL>cId5785<uTiL>.14) (-1092.74 213.0)" "[SmdPin] Dummy (<uTiL>cId4553<uTiL>.14) (-1093.02 213.0)" list(-1122.520000 203.000000) nil)@@@list("eric2_tseng" "2019/01/23 17:31:57" nil "p143000044-pc" "5s-ipcfl-cg.a00r")@@@list("doris_chen" "2019/01/24 12:51:11" nil "p16c000356-pc" "5s-ipcfl-cg.a00r-chk") | list("[Spacing] TOP" "3.SMD Pin to SMD Pin" "5 MIL [DEFAULT]" "OVERLAP" "" "DRC ERROR CLASS/TOP" "[SmdPin] Dummy (<uTiL>cId5785<uTiL>.13) (-1092.74 163.0)" "[SmdPin] Dummy (<uTiL>cId4553<uTiL>.13) (-1093.02 163.0)" list(-1122.520000 153.000000) nil)@@@list("eric2_tseng" "2019/01/23 17:31:56" nil "p143000044-pc" "5s-ipcfl-cg.a00r")@@@list("doris_chen" "2019/01/24 12:51:09" nil "p16c000356-pc" "5s-ipcfl-cg.a00r-chk") | list("[Spacing] TOP" "5.SMD Pin to SMD Pin" "5 MIL [DEFAULT]" "OVERLAP" "" "DRC ERROR CLASS/TOP" "[SmdPin] Dummy (<uTiL>cId5785<uTiL>.12) (-1092.74 113.0)" "[SmdPin] Dummy (<uTiL>cId4553<uTiL>.12) (-1093.02 113.0)" list(-1122.520000 103.000000) nil)@@@list("eric2_tseng" "2019/01/23 17:31:56" nil "p143000044-pc" "5s-ipcfl-cg.a00r")@@@list("doris_chen" "2019/01/24 12:51:10" nil "p16c000356-pc" "5s-ipcfl-cg.a00r-chk") | list("[Spacing] TOP" "2.SMD Pin to SMD Pin" "5 MIL [DEFAULT]" "OVERLAP" "" "DRC ERROR CLASS/TOP" "[SmdPin] Dummy (<uTiL>cId5785<uTiL>.11) (-1092.74 63.0)" "[SmdPin] Dummy (<uTiL>cId4553<uTiL>.11) (-1093.02 63.0)" list(-1122.520000 53.000000) nil)@@@list("eric2_tseng" "2019/01/23 17:31:55" nil "p143000044-pc" "5s-ipcfl-cg.a00r")@@@list("doris_chen" "2019/01/24 12:51:09" nil "p16c000356-pc" "5s-ipcfl-cg.a00r-chk") | list("[Physical] TOP" "58.Pad/Pad Direct Connect" "NOT_ALLOWED [85OHM(DP_5|5/5|5.5/5/200)]" "ALL_ALLOWED" "" "DRC ERROR CLASS/TOP" "[SmdPin] USB_PN4_B2_R (<uTiL>cId3061<uTiL>.2) (-1123.0 3733.28)" "[SmdPin] USB_PN4_B2_R (<uTiL>cId3067<uTiL>.4) (-1120.66 3735.22)" list(-1120.660000 3735.220000) nil)@@@list("eric2_tseng" "2019/01/23 17:33:53" nil "p143000044-pc" "5s-ipcfl-cg.a00r")@@@list("doris_chen" "2019/01/24 12:51:43" nil "p16c000356-pc" "5s-ipcfl-cg.a00r-chk") | list("[Physical] TOP" "71.Pad/Pad Direct Connect" "NOT_ALLOWED [85OHM(DP_5|5/5|5.5/5/200)]" "ALL_ALLOWED" "" "DRC ERROR CLASS/TOP" "[SmdPin] USB_PN4_B2 (<uTiL>cId3061<uTiL>.1) (-1123.0 3688.0)" "[SmdPin] USB_PN4_B2 (<uTiL>cId3067<uTiL>.1) (-1120.66 3686.0)" list(-1120.660000 3686.000000) nil)@@@list("eric2_tseng" "2019/01/23 17:33:09" nil "p143000044-pc" "5s-ipcfl-cg.a00r")@@@list("doris_chen" "2019/01/24 12:51:54" nil "p16c000356-pc" "5s-ipcfl-cg.a00r-chk") | list("[Physical] TOP" "182.Pad/Pad Direct Connect" "NOT_ALLOWED [85OHM(DP_5|5/5|5.5/5/200)]" "ALL_ALLOWED" "" "DRC ERROR CLASS/TOP" "[SmdPin] USB_PP4_B2 (<uTiL>cId3061<uTiL>.3) (-1097.4 3688.0)" "[SmdPin] USB_PP4_B2 (<uTiL>cId3067<uTiL>.2) (-1099.0 3686.0)" list(-1099.000000 3686.000000) nil)@@@list("eric2_tseng" "2019/01/23 17:33:53" nil "p143000044-pc" "5s-ipcfl-cg.a00r")@@@list("doris_chen" "2019/01/24 12:52:56" nil "p16c000356-pc" "5s-ipcfl-cg.a00r-chk") | list("[Physical] TOP" "89.Pad/Pad Direct Connect" "NOT_ALLOWED [85OHM(DP_5|5/5|5.5/5/200)]" "ALL_ALLOWED" "" "DRC ERROR CLASS/TOP" "[SmdPin] USB_PP4_B2_R (<uTiL>cId3067<uTiL>.3) (-1099.0 3735.22)" "[SmdPin] USB_PP4_B2_R (<uTiL>cId3061<uTiL>.4) (-1097.4 3733.28)" list(-1097.400000 3733.280000) nil)@@@list("eric2_tseng" "2019/01/23 17:34:08" nil "p143000044-pc" "5s-ipcfl-cg.a00r")@@@list("doris_chen" "2019/01/24 12:52:04" nil "p16c000356-pc" "5s-ipcfl-cg.a00r-chk") | list("[Physical] TOP" "84.Pad/Pad Direct Connect" "NOT_ALLOWED [50OHM(5)]" "ALL_ALLOWED" "" "DRC ERROR CLASS/TOP" "[SmdPin] R_SPI_CK (<uTiL>cId4553<uTiL>.16) (-1093.02 313.0)" "[SmdPin] R_SPI_CK (<uTiL>cId5785<uTiL>.16) (-1092.74 313.0)" list(-1092.740000 313.000000) nil)@@@list("eric2_tseng" "2019/01/23 17:34:07" nil "p143000044-pc" "5s-ipcfl-cg.a00r")@@@list("doris_chen" "2019/01/24 12:52:01" nil "p16c000356-pc" "5s-ipcfl-cg.a00r-chk") | list("[Physical] TOP" "157.Pad/Pad Direct Connect" "NOT_ALLOWED [50OHM(5)]" "ALL_ALLOWED" "" "DRC ERROR CLASS/TOP" "[SmdPin] R_SPI_IO0 (<uTiL>cId4553<uTiL>.15) (-1093.02 263.0)" "[SmdPin] R_SPI_IO0 (<uTiL>cId5785<uTiL>.15) (-1092.74 263.0)" list(-1092.740000 263.000000) nil)@@@list("eric2_tseng" "2019/01/23 17:33:28" nil "p143000044-pc" "5s-ipcfl-cg.a00r")@@@list("doris_chen" "2019/01/24 12:52:43" nil "p16c000356-pc" "5s-ipcfl-cg.a00r-chk") | list("[Physical] TOP" "158.Pad/Pad Direct Connect" "NOT_ALLOWED [(GND_20)]" "ALL_ALLOWED" "" "DRC ERROR CLASS/TOP" "[SmdPin] GND (<uTiL>cId4553<uTiL>.10) (-1093.02 13.0)" "[SmdPin] GND (<uTiL>cId5785<uTiL>.10) (-1092.74 13.0)" list(-1092.740000 13.000000) nil)@@@list("eric2_tseng" "2019/01/23 17:33:19" nil "p143000044-pc" "5s-ipcfl-cg.a00r")@@@list("doris_chen" "2019/01/24 12:52:44" nil "p16c000356-pc" "5s-ipcfl-cg.a00r-chk") | list("[Physical] TOP" "85.Pad/Pad Direct Connect" "NOT_ALLOWED [50OHM(5)]" "ALL_ALLOWED" "" "DRC ERROR CLASS/TOP" "[SmdPin] R_SPI_IO2_R (<uTiL>cId4553<uTiL>.9) (-1093.02 -37.0)" "[SmdPin] R_SPI_IO2_R (<uTiL>cId5785<uTiL>.9) (-1092.74 -37.0)" list(-1092.740000 -37.000000) nil)@@@list("eric2_tseng" "2019/01/23 17:34:05" nil "p143000044-pc" "5s-ipcfl-cg.a00r")@@@list("doris_chen" "2019/01/24 12:52:01" nil "p16c000356-pc" "5s-ipcfl-cg.a00r-chk") | list("[Physical] TOP" "181.Pad/Pad Direct Connect" "NOT_ALLOWED [85OHM(DP_5|5/5|5.5/5/200)]" "ALL_ALLOWED" "" "DRC ERROR CLASS/TOP" "[SmdPin] USB_PN3_B1_R (<uTiL>cId4872<uTiL>.2) (-1062.23 3733.92)" "[SmdPin] USB_PN3_B1_R (<uTiL>cId4781<uTiL>.4) (-1059.83 3735.61)" list(-1059.830000 3735.610000) nil)@@@list("eric2_tseng" "2019/01/23 17:34:22" nil "p143000044-pc" "5s-ipcfl-cg.a00r")@@@list("doris_chen" "2019/01/24 12:52:56" nil "p16c000356-pc" "5s-ipcfl-cg.a00r-chk") | list("[Physical] TOP" "93.Pad/Pad Direct Connect" "NOT_ALLOWED [85OHM(DP_5|5/5|5.5/5/200)]" "ALL_ALLOWED" "" "DRC ERROR CLASS/TOP" "[SmdPin] USB_PN3_B1 (<uTiL>cId4872<uTiL>.1) (-1062.23 3688.64)" "[SmdPin] USB_PN3_B1 (<uTiL>cId4781<uTiL>.1) (-1059.83 3686.39)" list(-1059.830000 3686.390000) nil)@@@list("eric2_tseng" "2019/01/23 17:33:10" nil "p143000044-pc" "5s-ipcfl-cg.a00r")@@@list("doris_chen" "2019/01/24 12:52:06" nil "p16c000356-pc" "5s-ipcfl-cg.a00r-chk") | list("[Physical] TOP" "180.Pad/Pad Direct Connect" "NOT_ALLOWED [85OHM(DP_5|5/5|5.5/5/200)]" "ALL_ALLOWED" "" "DRC ERROR CLASS/TOP" "[SmdPin] USB_PP3_B1_R (<uTiL>cId4872<uTiL>.4) (-1036.63 3733.92)" "[SmdPin] USB_PP3_B1_R (<uTiL>cId4781<uTiL>.3) (-1038.17 3735.61)" list(-1038.170000 3735.610000) nil)@@@list("eric2_tseng" "2019/01/23 17:34:01" nil "p143000044-pc" "5s-ipcfl-cg.a00r")@@@list("doris_chen" "2019/01/24 12:52:55" nil "p16c000356-pc" "5s-ipcfl-cg.a00r-chk") | list("[Physical] TOP" "131.Pad/Pad Direct Connect" "NOT_ALLOWED [85OHM(DP_5|5/5|5.5/5/200)]" "ALL_ALLOWED" "" "DRC ERROR CLASS/TOP" "[SmdPin] USB_PP3_B1 (<uTiL>cId4872<uTiL>.3) (-1036.63 3688.64)" "[SmdPin] USB_PP3_B1 (<uTiL>cId4781<uTiL>.2) (-1038.17 3686.39)" list(-1038.170000 3686.390000) nil)@@@list("eric2_tseng" "2019/01/23 17:33:41" nil "p143000044-pc" "5s-ipcfl-cg.a00r")@@@list("doris_chen" "2019/01/24 12:52:26" nil "p16c000356-pc" "5s-ipcfl-cg.a00r-chk") | list("[Physical] TOP" "79.Pad/Pad Direct Connect" "NOT_ALLOWED [85OHM(DP_5|5/5|5.5/5/200)]" "ALL_ALLOWED" "" "DRC ERROR CLASS/TOP" "[SmdPin] USB3_TXP2_F2 (<uTiL>cId3546<uTiL>.3) (-1016.81 -1839.68)" "[SmdPin] USB3_TXP2_F2 (<uTiL>cId3608<uTiL>.2) (-1014.84 -1839.19)" list(-1014.840000 -1839.190000) nil)@@@list("eric2_tseng" "2019/01/23 17:34:25" nil "p143000044-pc" "5s-ipcfl-cg.a00r")@@@list("doris_chen" "2019/01/24 12:51:58" nil "p16c000356-pc" "5s-ipcfl-cg.a00r-chk") | list("[Physical] TOP" "107.Pad/Pad Direct Connect" "NOT_ALLOWED [85OHM(DP_5|5/5|5.5/5/200)]" "ALL_ALLOWED" "" "DRC ERROR CLASS/TOP" "[SmdPin] USB3_TXP2_F2_R (<uTiL>cId3546<uTiL>.4) (-1016.81 -1862.32)" "[SmdPin] USB3_TXP2_F2_R (<uTiL>cId3608<uTiL>.1) (-1014.84 -1862.81)" list(-1014.840000 -1862.810000) nil)@@@list("eric2_tseng" "2019/01/23 17:34:25" nil "p143000044-pc" "5s-ipcfl-cg.a00r")@@@list("doris_chen" "2019/01/24 12:52:13" nil "p16c000356-pc" "5s-ipcfl-cg.a00r-chk") | list("[Physical] TOP" "73.Pad/Pad Direct Connect" "NOT_ALLOWED [85OHM(DP_5|5/5|5.5/5/200)]" "ALL_ALLOWED" "" "DRC ERROR CLASS/TOP" "[SmdPin] USB3_TXN2_F2 (<uTiL>cId3546<uTiL>.1) (-993.19 -1839.68)" "[SmdPin] USB3_TXN2_F2 (<uTiL>cId3608<uTiL>.3) (-995.16 -1839.19)" list(-995.160000 -1839.190000) nil)@@@list("eric2_tseng" "2019/01/23 17:34:13" nil "p143000044-pc" "5s-ipcfl-cg.a00r")@@@list("doris_chen" "2019/01/24 12:51:55" nil "p16c000356-pc" "5s-ipcfl-cg.a00r-chk") | list("[Physical] TOP" "136.Pad/Pad Direct Connect" "NOT_ALLOWED [85OHM(DP_5|5/5|5.5/5/200)]" "ALL_ALLOWED" "" "DRC ERROR CLASS/TOP" "[SmdPin] USB3_TXN2_F2_R (<uTiL>cId3546<uTiL>.2) (-993.19 -1862.32)" "[SmdPin] USB3_TXN2_F2_R (<uTiL>cId3608<uTiL>.4) (-995.16 -1862.81)" list(-995.160000 -1862.810000) nil)@@@list("eric2_tseng" "2019/01/23 17:34:26" nil "p143000044-pc" "5s-ipcfl-cg.a00r")@@@list("doris_chen" "2019/01/24 12:52:29" nil "p16c000356-pc" "5s-ipcfl-cg.a00r-chk") | list("[Physical] TOP" "106.Pad/Pad Direct Connect" "NOT_ALLOWED [85OHM(DP_5|5/5|5.5/5/200)]" "ALL_ALLOWED" "" "DRC ERROR CLASS/TOP" "[SmdPin] USB3_RXP2_F2_R (<uTiL>cId5845<uTiL>.1) (-949.84 -1866.81)" "[SmdPin] USB3_RXP2_F2_R (<uTiL>cId3545<uTiL>.4) (-951.81 -1866.32)" list(-951.810000 -1866.320000) nil)@@@list("eric2_tseng" "2019/01/23 17:33:12" nil "p143000044-pc" "5s-ipcfl-cg.a00r")@@@list("doris_chen" "2019/01/24 12:52:13" nil "p16c000356-pc" "5s-ipcfl-cg.a00r-chk") | list("[Physical] TOP" "78.Pad/Pad Direct Connect" "NOT_ALLOWED [85OHM(DP_5|5/5|5.5/5/200)]" "ALL_ALLOWED" "" "DRC ERROR CLASS/TOP" "[SmdPin] USB3_RXP2_F2 (<uTiL>cId3545<uTiL>.3) (-951.81 -1843.68)" "[SmdPin] USB3_RXP2_F2 (<uTiL>cId5845<uTiL>.2) (-949.84 -1843.19)" list(-949.840000 -1843.190000) nil)@@@list("eric2_tseng" "2019/01/23 17:34:04" nil "p143000044-pc" "5s-ipcfl-cg.a00r")@@@list("doris_chen" "2019/01/24 12:51:57" nil "p16c000356-pc" "5s-ipcfl-cg.a00r-chk") | list("[Physical] TOP" "137.Pad/Pad Direct Connect" "NOT_ALLOWED [85OHM(DP_5|5/5|5.5/5/200)]" "ALL_ALLOWED" "" "DRC ERROR CLASS/TOP" "[SmdPin] USB3_RXN2_F2_R (<uTiL>cId3545<uTiL>.2) (-928.19 -1866.32)" "[SmdPin] USB3_RXN2_F2_R (<uTiL>cId5845<uTiL>.4) (-930.16 -1866.81)" list(-930.160000 -1866.810000) nil)@@@list("eric2_tseng" "2019/01/23 17:33:45" nil "p143000044-pc" "5s-ipcfl-cg.a00r")@@@list("doris_chen" "2019/01/24 12:52:30" nil "p16c000356-pc" "5s-ipcfl-cg.a00r-chk") | list("[Physical] TOP" "105.Pad/Pad Direct Connect" "NOT_ALLOWED [85OHM(DP_5|5/5|5.5/5/200)]" "ALL_ALLOWED" "" "DRC ERROR CLASS/TOP" "[SmdPin] USB3_RXN2_F2 (<uTiL>cId5845<uTiL>.3) (-930.16 -1843.19)" "[SmdPin] USB3_RXN2_F2 (<uTiL>cId3545<uTiL>.1) (-928.19 -1843.68)" list(-928.190000 -1843.680000) nil)@@@list("eric2_tseng" "2019/01/23 17:33:54" nil "p143000044-pc" "5s-ipcfl-cg.a00r")@@@list("doris_chen" "2019/01/24 12:52:12" nil "p16c000356-pc" "5s-ipcfl-cg.a00r-chk") | list("[Physical] TOP" "122.Pad/Pad Direct Connect" "NOT_ALLOWED [(PWR_20)]" "ALL_ALLOWED" "" "DRC ERROR CLASS/TOP" "[SmdPin] +3P3VA (<uTiL>cId2237<uTiL>.1) (-899.0 -1237.56)" "[SmdPin] +3P3VA (<uTiL>cId2358<uTiL>.1) (-898.0 -1288.5)" list(-898.000000 -1288.500000) nil)@@@list("eric2_tseng" "2019/01/23 17:34:19" nil "p143000044-pc" "5s-ipcfl-cg.a00r")@@@list("doris_chen" "2019/01/24 12:52:22" nil "p16c000356-pc" "5s-ipcfl-cg.a00r-chk") | list("[Physical] TOP" "160.Pad/Pad Direct Connect" "NOT_ALLOWED [85OHM(DP_5|5/5|5.5/5/200)]" "ALL_ALLOWED" "" "DRC ERROR CLASS/TOP" "[SmdPin] USB_PP2_F2 (<uTiL>cId2790<uTiL>.2) (-845.55 -1894.82)" "[SmdPin] USB_PP2_F2 (<uTiL>cId6092<uTiL>.3) (-847.52 -1896.79)" list(-847.520000 -1896.790000) nil)@@@list("eric2_tseng" "2019/01/23 17:34:08" nil "p143000044-pc" "5s-ipcfl-cg.a00r")@@@list("doris_chen" "2019/01/24 12:52:45" nil "p16c000356-pc" "5s-ipcfl-cg.a00r-chk") | list("[Physical] TOP" "70.Pad/Pad Direct Connect" "NOT_ALLOWED [85OHM(DP_5|5/5|5.5/5/200)]" "ALL_ALLOWED" "" "DRC ERROR CLASS/TOP" "[SmdPin] USB_PP2_F2_R (<uTiL>cId6092<uTiL>.4) (-847.52 -1942.07)" "[SmdPin] USB_PP2_F2_R (<uTiL>cId2790<uTiL>.3) (-845.55 -1944.04)" list(-845.550000 -1944.040000) nil)@@@list("eric2_tseng" "2019/01/23 17:34:18" nil "p143000044-pc" "5s-ipcfl-cg.a00r")@@@list("doris_chen" "2019/01/24 12:51:53" nil "p16c000356-pc" "5s-ipcfl-cg.a00r-chk") | list("[Physical] TOP" "179.Pad/Pad Direct Connect" "NOT_ALLOWED [85OHM(DP_5|5/5|5.5/5/200)]" "ALL_ALLOWED" "" "DRC ERROR CLASS/TOP" "[SmdPin] USB_PN2_F2_R (<uTiL>cId6092<uTiL>.2) (-821.92 -1942.07)" "[SmdPin] USB_PN2_F2_R (<uTiL>cId2790<uTiL>.4) (-823.89 -1944.04)" list(-823.890000 -1944.040000) nil)@@@list("eric2_tseng" "2019/01/23 17:33:53" nil "p143000044-pc" "5s-ipcfl-cg.a00r")@@@list("doris_chen" "2019/01/24 12:52:55" nil "p16c000356-pc" "5s-ipcfl-cg.a00r-chk") | list("[Physical] TOP" "88.Pad/Pad Direct Connect" "NOT_ALLOWED [85OHM(DP_5|5/5|5.5/5/200)]" "ALL_ALLOWED" "" "DRC ERROR CLASS/TOP" "[SmdPin] USB_PN2_F2 (<uTiL>cId2790<uTiL>.1) (-823.89 -1894.82)" "[SmdPin] USB_PN2_F2 (<uTiL>cId6092<uTiL>.1) (-821.92 -1896.79)" list(-821.920000 -1896.790000) nil)@@@list("eric2_tseng" "2019/01/23 17:33:43" nil "p143000044-pc" "5s-ipcfl-cg.a00r")@@@list("doris_chen" "2019/01/24 12:52:03" nil "p16c000356-pc" "5s-ipcfl-cg.a00r-chk") | list("[Spacing-SameNet] TOP" "37.Thru Pin to Thru Pin Same Net" "5 MIL [DEFAULT]" "OVERLAP" "" "DRC ERROR CLASS/TOP" "[ThruPin] GND (<uTiL>cId5726<uTiL>.1) (-794.25 1790.95)" "[ThruPin] GND (<uTiL>cId6011<uTiL>.2) (-794.25 1790.95)" list(-794.250000 1790.950000) nil)@@@list("eric2_tseng" "2019/01/23 17:32:53" nil "p143000044-pc" "5s-ipcfl-cg.a00r")@@@list("doris_chen" "2019/01/24 12:51:32" nil "p16c000356-pc" "5s-ipcfl-cg.a00r-chk") | list("[Physical] TOP" "185.Pad/Pad Direct Connect" "NOT_ALLOWED [85OHM(DP_5|5/5|5.5/5/200)]" "ALL_ALLOWED" "" "DRC ERROR CLASS/TOP" "[SmdPin] USB_PP1_F1 (<uTiL>cId637<uTiL>.3) (-782.37 -1897.08)" "[SmdPin] USB_PP1_F1 (<uTiL>cId703<uTiL>.2) (-780.4 -1895.11)" list(-780.400000 -1895.110000) nil)@@@list("eric2_tseng" "2019/01/23 17:34:03" nil "p143000044-pc" "5s-ipcfl-cg.a00r")@@@list("doris_chen" "2019/01/24 12:52:58" nil "p16c000356-pc" "5s-ipcfl-cg.a00r-chk") | list("[Physical] TOP" "133.Pad/Pad Direct Connect" "NOT_ALLOWED [85OHM(DP_5|5/5|5.5/5/200)]" "ALL_ALLOWED" "" "DRC ERROR CLASS/TOP" "[SmdPin] USB_PP1_F1_R (<uTiL>cId637<uTiL>.4) (-782.37 -1942.36)" "[SmdPin] USB_PP1_F1_R (<uTiL>cId703<uTiL>.3) (-780.4 -1944.33)" list(-780.400000 -1944.330000) nil)@@@list("eric2_tseng" "2019/01/23 17:33:44" nil "p143000044-pc" "5s-ipcfl-cg.a00r")@@@list("doris_chen" "2019/01/24 12:52:27" nil "p16c000356-pc" "5s-ipcfl-cg.a00r-chk") | list("[Spacing-SameNet] TOP" "38.Thru Pin to Thru Pin Same Net" "5 MIL [DEFAULT]" "OVERLAP" "" "DRC ERROR CLASS/TOP" "[ThruPin] GND (<uTiL>cId5726<uTiL>.2) (-794.25 1990.95)" "[ThruPin] GND (<uTiL>cId6011<uTiL>.1) (-794.25 1990.95)" list(-763.250000 1990.950000) nil)@@@list("eric2_tseng" "2019/01/23 17:32:54" nil "p143000044-pc" "5s-ipcfl-cg.a00r")@@@list("doris_chen" "2019/01/24 12:51:33" nil "p16c000356-pc" "5s-ipcfl-cg.a00r-chk") | list("[Physical] TOP" "77.Pad/Pad Direct Connect" "NOT_ALLOWED [85OHM(DP_5|5/5|5.5/5/200)]" "ALL_ALLOWED" "" "DRC ERROR CLASS/TOP" "[SmdPin] USB_PN1_F1_R (<uTiL>cId637<uTiL>.2) (-756.77 -1942.36)" "[SmdPin] USB_PN1_F1_R (<uTiL>cId703<uTiL>.4) (-758.74 -1944.33)" list(-758.740000 -1944.330000) nil)@@@list("eric2_tseng" "2019/01/23 17:34:23" nil "p143000044-pc" "5s-ipcfl-cg.a00r")@@@list("doris_chen" "2019/01/24 12:51:57" nil "p16c000356-pc" "5s-ipcfl-cg.a00r-chk") | list("[Physical] TOP" "62.Pad/Pad Direct Connect" "NOT_ALLOWED [85OHM(DP_5|5/5|5.5/5/200)]" "ALL_ALLOWED" "" "DRC ERROR CLASS/TOP" "[SmdPin] USB_PN1_F1 (<uTiL>cId703<uTiL>.1) (-758.74 -1895.11)" "[SmdPin] USB_PN1_F1 (<uTiL>cId637<uTiL>.1) (-756.77 -1897.08)" list(-756.770000 -1897.080000) nil)@@@list("eric2_tseng" "2019/01/23 17:34:05" nil "p143000044-pc" "5s-ipcfl-cg.a00r")@@@list("doris_chen" "2019/01/24 12:51:46" nil "p16c000356-pc" "5s-ipcfl-cg.a00r-chk") | list("[Physical] TOP" "132.Pad/Pad Direct Connect" "NOT_ALLOWED [85OHM(DP_5|5/5|5.5/5/200)]" "ALL_ALLOWED" "" "DRC ERROR CLASS/TOP" "[SmdPin] USB3_RXN4_B2_R (<uTiL>cId3060<uTiL>.2) (-758.18 3300.25)" "[SmdPin] USB3_RXN4_B2_R (<uTiL>cId3064<uTiL>.4) (-756.21 3300.74)" list(-756.210000 3300.740000) nil)@@@list("eric2_tseng" "2019/01/23 17:34:02" nil "p143000044-pc" "5s-ipcfl-cg.a00r")@@@list("doris_chen" "2019/01/24 12:52:27" nil "p16c000356-pc" "5s-ipcfl-cg.a00r-chk") | list("[Physical] TOP" "183.Pad/Pad Direct Connect" "NOT_ALLOWED [85OHM(DP_5|5/5|5.5/5/200)]" "ALL_ALLOWED" "" "DRC ERROR CLASS/TOP" "[SmdPin] USB3_RXN4_B2 (<uTiL>cId3060<uTiL>.1) (-758.18 3277.61)" "[SmdPin] USB3_RXN4_B2 (<uTiL>cId3064<uTiL>.3) (-756.21 3277.12)" list(-756.210000 3277.120000) nil)@@@list("eric2_tseng" "2019/01/23 17:34:22" nil "p143000044-pc" "5s-ipcfl-cg.a00r")@@@list("doris_chen" "2019/01/24 12:52:57" nil "p16c000356-pc" "5s-ipcfl-cg.a00r-chk") | list("[Physical] TOP" "184.Pad/Pad Direct Connect" "NOT_ALLOWED [85OHM(DP_5|5/5|5.5/5/200)]" "ALL_ALLOWED" "" "DRC ERROR CLASS/TOP" "[SmdPin] USB3_RXP4_B2_R (<uTiL>cId3060<uTiL>.4) (-734.56 3300.25)" "[SmdPin] USB3_RXP4_B2_R (<uTiL>cId3064<uTiL>.1) (-736.53 3300.74)" list(-736.530000 3300.740000) nil)@@@list("eric2_tseng" "2019/01/23 17:34:02" nil "p143000044-pc" "5s-ipcfl-cg.a00r")@@@list("doris_chen" "2019/01/24 12:52:58" nil "p16c000356-pc" "5s-ipcfl-cg.a00r-chk") | list("[Physical] TOP" "81.Pad/Pad Direct Connect" "NOT_ALLOWED [85OHM(DP_5|5/5|5.5/5/200)]" "ALL_ALLOWED" "" "DRC ERROR CLASS/TOP" "[SmdPin] USB3_RXP4_B2 (<uTiL>cId3064<uTiL>.2) (-736.53 3277.12)" "[SmdPin] USB3_RXP4_B2 (<uTiL>cId3060<uTiL>.3) (-734.56 3277.61)" list(-734.560000 3277.610000) nil)@@@list("eric2_tseng" "2019/01/23 17:33:27" nil "p143000044-pc" "5s-ipcfl-cg.a00r")@@@list("doris_chen" "2019/01/24 12:51:59" nil "p16c000356-pc" "5s-ipcfl-cg.a00r-chk") | list("[Physical] TOP" "124.Pad/Pad Direct Connect" "NOT_ALLOWED [(PWR_20)]" "ALL_ALLOWED" "" "DRC ERROR CLASS/TOP" "[SmdPin] +1P05VSB (<uTiL>cId2357<uTiL>.1) (-690.0 980.5)" "[SmdPin] +1P05VSB (<uTiL>cId4197<uTiL>.1) (-691.96 971.24)" list(-691.960000 971.240000) nil)@@@list("eric2_tseng" "2019/01/23 17:33:59" nil "p143000044-pc" "5s-ipcfl-cg.a00r")@@@list("doris_chen" "2019/01/24 12:52:23" nil "p16c000356-pc" "5s-ipcfl-cg.a00r-chk") | list("[Physical] TOP" "144.Pad/Pad Direct Connect" "NOT_ALLOWED [85OHM(DP_5|5/5|5.5/5/200)]" "ALL_ALLOWED" "" "DRC ERROR CLASS/TOP" "[SmdPin] USB3_TXN4_B2 (<uTiL>cId3065<uTiL>.3) (-682.92 3279.47)" "[SmdPin] USB3_TXN4_B2 (<uTiL>cId3059<uTiL>.1) (-684.89 3279.96)" list(-684.890000 3279.960000) nil)@@@list("eric2_tseng" "2019/01/23 17:34:03" nil "p143000044-pc" "5s-ipcfl-cg.a00r")@@@list("doris_chen" "2019/01/24 12:52:34" nil "p16c000356-pc" "5s-ipcfl-cg.a00r-chk") | list("[Physical] TOP" "60.Pad/Pad Direct Connect" "NOT_ALLOWED [85OHM(DP_5|5/5|5.5/5/200)]" "ALL_ALLOWED" "" "DRC ERROR CLASS/TOP" "[SmdPin] USB3_TXN4_B2_R (<uTiL>cId3059<uTiL>.2) (-684.89 3302.6)" "[SmdPin] USB3_TXN4_B2_R (<uTiL>cId3065<uTiL>.4) (-682.92 3303.09)" list(-682.920000 3303.090000) nil)@@@list("eric2_tseng" "2019/01/23 17:33:55" nil "p143000044-pc" "5s-ipcfl-cg.a00r")@@@list("doris_chen" "2019/01/24 12:51:44" nil "p16c000356-pc" "5s-ipcfl-cg.a00r-chk") | list("[Physical] TOP" "134.Pad/Pad Direct Connect" "NOT_ALLOWED [85OHM(DP_5|5/5|5.5/5/200)]" "ALL_ALLOWED" "" "DRC ERROR CLASS/TOP" "[SmdPin] USB3_TXP4_B2_R (<uTiL>cId3059<uTiL>.4) (-661.27 3302.6)" "[SmdPin] USB3_TXP4_B2_R (<uTiL>cId3065<uTiL>.1) (-663.24 3303.09)" list(-663.240000 3303.090000) nil)@@@list("eric2_tseng" "2019/01/23 17:33:27" nil "p143000044-pc" "5s-ipcfl-cg.a00r")@@@list("doris_chen" "2019/01/24 12:52:28" nil "p16c000356-pc" "5s-ipcfl-cg.a00r-chk") | list("[Physical] TOP" "186.Pad/Pad Direct Connect" "NOT_ALLOWED [85OHM(DP_5|5/5|5.5/5/200)]" "ALL_ALLOWED" "" "DRC ERROR CLASS/TOP" "[SmdPin] USB3_TXP4_B2 (<uTiL>cId3059<uTiL>.3) (-661.27 3279.96)" "[SmdPin] USB3_TXP4_B2 (<uTiL>cId3065<uTiL>.2) (-663.24 3279.47)" list(-663.240000 3279.470000) nil)@@@list("eric2_tseng" "2019/01/23 17:33:10" nil "p143000044-pc" "5s-ipcfl-cg.a00r")@@@list("doris_chen" "2019/01/24 12:52:59" nil "p16c000356-pc" "5s-ipcfl-cg.a00r-chk") | list("[Physical] TOP" "50.Pad/Pad Direct Connect" "NOT_ALLOWED [85OHM(DP_5|5/5|5.5/5/200)]" "ALL_ALLOWED" "" "DRC ERROR CLASS/TOP" "[SmdPin] USB3_TXP1_F1 (<uTiL>cId639<uTiL>.3) (-441.81 -1838.68)" "[SmdPin] USB3_TXP1_F1 (<uTiL>cId679<uTiL>.2) (-439.84 -1838.19)" list(-439.840000 -1838.190000) nil)@@@list("eric2_tseng" "2019/01/23 17:34:14" nil "p143000044-pc" "5s-ipcfl-cg.a00r")@@@list("doris_chen" "2019/01/24 12:51:39" nil "p16c000356-pc" "5s-ipcfl-cg.a00r-chk") | list("[Physical] TOP" "51.Pad/Pad Direct Connect" "NOT_ALLOWED [85OHM(DP_5|5/5|5.5/5/200)]" "ALL_ALLOWED" "" "DRC ERROR CLASS/TOP" "[SmdPin] USB3_TXP1_F1_R (<uTiL>cId639<uTiL>.4) (-441.81 -1861.32)" "[SmdPin] USB3_TXP1_F1_R (<uTiL>cId679<uTiL>.1) (-439.84 -1861.81)" list(-439.840000 -1861.810000) nil)@@@list("eric2_tseng" "2019/01/23 17:33:28" nil "p143000044-pc" "5s-ipcfl-cg.a00r")@@@list("doris_chen" "2019/01/24 12:51:40" nil "p16c000356-pc" "5s-ipcfl-cg.a00r-chk") | list("[Physical] TOP" "162.Pad/Pad Direct Connect" "NOT_ALLOWED [(PWR_20)]" "ALL_ALLOWED" "" "DRC ERROR CLASS/TOP" "[SmdPin] +0P95V_CPUIO (<uTiL>cId5389<uTiL>.1) (-375.6 1306.0)" "[SmdPin] +0P95V_CPUIO (<uTiL>cId5432<uTiL>.2) (-430.5 1323.0)" list(-430.500000 1323.000000) nil)@@@list("eric2_tseng" "2019/01/23 17:34:17" nil "p143000044-pc" "5s-ipcfl-cg.a00r")@@@list("doris_chen" "2019/01/24 12:52:46" nil "p16c000356-pc" "5s-ipcfl-cg.a00r-chk") | list("[Physical] TOP" "111.Pad/Pad Direct Connect" "NOT_ALLOWED [85OHM(DP_5|5/5|5.5/5/200)]" "ALL_ALLOWED" "" "DRC ERROR CLASS/TOP" "[SmdPin] USB3_TXN1_F1 (<uTiL>cId679<uTiL>.3) (-420.16 -1838.19)" "[SmdPin] USB3_TXN1_F1 (<uTiL>cId639<uTiL>.1) (-418.19 -1838.68)" list(-418.190000 -1838.680000) nil)@@@list("eric2_tseng" "2019/01/23 17:33:54" nil "p143000044-pc" "5s-ipcfl-cg.a00r")@@@list("doris_chen" "2019/01/24 12:52:16" nil "p16c000356-pc" "5s-ipcfl-cg.a00r-chk") | list("[Physical] TOP" "82.Pad/Pad Direct Connect" "NOT_ALLOWED [85OHM(DP_5|5/5|5.5/5/200)]" "ALL_ALLOWED" "" "DRC ERROR CLASS/TOP" "[SmdPin] USB3_TXN1_F1_R (<uTiL>cId679<uTiL>.4) (-420.16 -1861.81)" "[SmdPin] USB3_TXN1_F1_R (<uTiL>cId639<uTiL>.2) (-418.19 -1861.32)" list(-418.190000 -1861.320000) nil)@@@list("eric2_tseng" "2019/01/23 17:33:15" nil "p143000044-pc" "5s-ipcfl-cg.a00r")@@@list("doris_chen" "2019/01/24 12:52:00" nil "p16c000356-pc" "5s-ipcfl-cg.a00r-chk") | list("[Physical] TOP" "138.Pad/Pad Direct Connect" "NOT_ALLOWED [85OHM(DP_5|5/5|5.5/5/200)]" "ALL_ALLOWED" "" "DRC ERROR CLASS/TOP" "[SmdPin] USB3_RXP1_F1 (<uTiL>cId678<uTiL>.2) (-369.84 -1838.19)" "[SmdPin] USB3_RXP1_F1 (<uTiL>cId638<uTiL>.3) (-371.81 -1838.68)" list(-371.810000 -1838.680000) nil)@@@list("eric2_tseng" "2019/01/23 17:34:04" nil "p143000044-pc" "5s-ipcfl-cg.a00r")@@@list("doris_chen" "2019/01/24 12:52:30" nil "p16c000356-pc" "5s-ipcfl-cg.a00r-chk") | list("[Physical] TOP" "80.Pad/Pad Direct Connect" "NOT_ALLOWED [85OHM(DP_5|5/5|5.5/5/200)]" "ALL_ALLOWED" "" "DRC ERROR CLASS/TOP" "[SmdPin] USB3_RXP1_F1_R (<uTiL>cId638<uTiL>.4) (-371.81 -1861.32)" "[SmdPin] USB3_RXP1_F1_R (<uTiL>cId678<uTiL>.1) (-369.84 -1861.81)" list(-369.840000 -1861.810000) nil)@@@list("eric2_tseng" "2019/01/23 17:34:26" nil "p143000044-pc" "5s-ipcfl-cg.a00r")@@@list("doris_chen" "2019/01/24 12:51:59" nil "p16c000356-pc" "5s-ipcfl-cg.a00r-chk") | list("[Spacing] TOP" "10.Drill Hole to Drill Hole" "8 MIL [DEFAULT]" "OVERLAP" "" "DRC ERROR CLASS/TOP" "[ThruPin] Dummy (<uTiL>cId3746<uTiL>.2) (-359.85 883.07)" "[ThruPin] Dummy (<uTiL>cId3746<uTiL>.1) (-359.85 932.28)" list(-359.850000 847.780000) nil)@@@list("eric2_tseng" "2019/01/23 17:31:59" nil "p143000044-pc" "5s-ipcfl-cg.a00r")@@@list("doris_chen" "2019/01/24 12:51:13" nil "p16c000356-pc" "5s-ipcfl-cg.a00r-chk") | list("[Physical] TOP" "108.Pad/Pad Direct Connect" "NOT_ALLOWED [85OHM(DP_5|5/5|5.5/5/200)]" "ALL_ALLOWED" "" "DRC ERROR CLASS/TOP" "[SmdPin] USB3_RXN1_F1 (<uTiL>cId638<uTiL>.1) (-348.19 -1838.68)" "[SmdPin] USB3_RXN1_F1 (<uTiL>cId678<uTiL>.3) (-350.16 -1838.19)" list(-350.160000 -1838.190000) nil)@@@list("eric2_tseng" "2019/01/23 17:33:55" nil "p143000044-pc" "5s-ipcfl-cg.a00r")@@@list("doris_chen" "2019/01/24 12:52:14" nil "p16c000356-pc" "5s-ipcfl-cg.a00r-chk") | list("[Physical] TOP" "143.Pad/Pad Direct Connect" "NOT_ALLOWED [85OHM(DP_5|5/5|5.5/5/200)]" "ALL_ALLOWED" "" "DRC ERROR CLASS/TOP" "[SmdPin] USB3_RXN1_F1_R (<uTiL>cId678<uTiL>.4) (-350.16 -1861.81)" "[SmdPin] USB3_RXN1_F1_R (<uTiL>cId638<uTiL>.2) (-348.19 -1861.32)" list(-348.190000 -1861.320000) nil)@@@list("eric2_tseng" "2019/01/23 17:34:14" nil "p143000044-pc" "5s-ipcfl-cg.a00r")@@@list("doris_chen" "2019/01/24 12:52:33" nil "p16c000356-pc" "5s-ipcfl-cg.a00r-chk") | list("[Spacing] TOP" "8.Drill Hole to Drill Hole" "8 MIL [DEFAULT]" "OVERLAP" "" "DRC ERROR CLASS/TOP" "[ThruPin] Dummy (<uTiL>cId864<uTiL>.1) (-334.64 -788.19)" "[ThruPin] Dummy (<uTiL>cId864<uTiL>.2) (-334.64 -868.11)" list(-334.640000 -866.690000) nil)@@@list("eric2_tseng" "2019/01/23 17:32:02" nil "p143000044-pc" "5s-ipcfl-cg.a00r")@@@list("doris_chen" "2019/01/24 12:51:12" nil "p16c000356-pc" "5s-ipcfl-cg.a00r-chk") | list("[Physical] TOP" "200.Pad/Pad Direct Connect" "NOT_ALLOWED [(PWR_20)]" "ALL_ALLOWED" "" "DRC ERROR CLASS/TOP" "[SmdPin] VCORE_+19V (<uTiL>cId5788<uTiL>.10) (265.0 3370.17)" "[ThruPin] VCORE_+19V (<uTiL>cId5788<uTiL>.19) (195.0 3371.17)" list(195.000000 3371.170000) nil)@@@list("eric2_tseng" "2019/01/23 17:33:18" nil "p143000044-pc" "5s-ipcfl-cg.a00r")@@@list("doris_chen" "2019/01/24 12:53:06" nil "p16c000356-pc" "5s-ipcfl-cg.a00r-chk") | list("[Physical] TOP" "56.Pad/Pad Direct Connect" "NOT_ALLOWED [(GND_20)]" "ALL_ALLOWED" "" "DRC ERROR CLASS/TOP" "[SmdPin] GND (<uTiL>cId5788<uTiL>.9) (265.0 3282.98)" "[ThruPin] GND (<uTiL>cId5788<uTiL>.12) (197.74 3323.2)" list(197.740000 3323.200000) nil)@@@list("eric2_tseng" "2019/01/23 17:33:24" nil "p143000044-pc" "5s-ipcfl-cg.a00r")@@@list("doris_chen" "2019/01/24 12:51:42" nil "p16c000356-pc" "5s-ipcfl-cg.a00r-chk") | list("[Physical] TOP" "112.Pad/Pad Direct Connect" "NOT_ALLOWED [(GND_20)]" "ALL_ALLOWED" "" "DRC ERROR CLASS/TOP" "[SmdPin] GND (<uTiL>cId5788<uTiL>.9) (265.0 3282.98)" "[ThruPin] GND (<uTiL>cId5788<uTiL>.11) (197.74 3243.2)" list(197.740000 3243.200000) nil)@@@list("eric2_tseng" "2019/01/23 17:33:29" nil "p143000044-pc" "5s-ipcfl-cg.a00r")@@@list("doris_chen" "2019/01/24 12:52:16" nil "p16c000356-pc" "5s-ipcfl-cg.a00r-chk") | list("[Physical] TOP" "146.Pad/Pad Direct Connect" "NOT_ALLOWED [(GND_20)]" "ALL_ALLOWED" "" "DRC ERROR CLASS/TOP" "[SmdPin] GND (<uTiL>cId5788<uTiL>.9) (265.0 3282.98)" "[ThruPin] GND (<uTiL>cId5788<uTiL>.14) (242.74 3323.2)" list(242.740000 3323.200000) nil)@@@list("eric2_tseng" "2019/01/23 17:33:24" nil "p143000044-pc" "5s-ipcfl-cg.a00r")@@@list("doris_chen" "2019/01/24 12:52:37" nil "p16c000356-pc" "5s-ipcfl-cg.a00r-chk") | list("[Physical] TOP" "54.Pad/Pad Direct Connect" "NOT_ALLOWED [(GND_20)]" "ALL_ALLOWED" "" "DRC ERROR CLASS/TOP" "[SmdPin] GND (<uTiL>cId5788<uTiL>.9) (265.0 3282.98)" "[ThruPin] GND (<uTiL>cId5788<uTiL>.13) (242.74 3243.2)" list(242.740000 3243.200000) nil)@@@list("eric2_tseng" "2019/01/23 17:33:23" nil "p143000044-pc" "5s-ipcfl-cg.a00r")@@@list("doris_chen" "2019/01/24 12:51:41" nil "p16c000356-pc" "5s-ipcfl-cg.a00r-chk") | list("[Physical] TOP" "63.Pad/Pad Direct Connect" "NOT_ALLOWED [(PWR_20)]" "ALL_ALLOWED" "" "DRC ERROR CLASS/TOP" "[SmdPin] CORE_PWM3_SW_S (<uTiL>cId4356<uTiL>.1) (258.28 3089.33)" "[SmdPin] CORE_PWM3_SW_S (<uTiL>cId4334<uTiL>.1) (258.0 3046.5)" list(258.000000 3046.500000) nil)@@@list("eric2_tseng" "2019/01/23 17:34:09" nil "p143000044-pc" "5s-ipcfl-cg.a00r")@@@list("doris_chen" "2019/01/24 12:51:49" nil "p16c000356-pc" "5s-ipcfl-cg.a00r-chk") | list("[Physical] TOP" "102.Pad/Pad Direct Connect" "NOT_ALLOWED [(PWR_20)]" "ALL_ALLOWED" "" "DRC ERROR CLASS/TOP" "[SmdPin] +VCORE (<uTiL>cId4335<uTiL>.1) (258.0 2886.5)" "[SmdPin] +VCORE (<uTiL>cId4356<uTiL>.2) (258.28 2845.23)" list(258.000000 2886.500000) nil)@@@list("eric2_tseng" "2019/01/23 17:33:13" nil "p143000044-pc" "5s-ipcfl-cg.a00r")@@@list("doris_chen" "2019/01/24 12:52:10" nil "p16c000356-pc" "5s-ipcfl-cg.a00r-chk") | list("[Physical] TOP" "83.Pad/Pad Direct Connect" "NOT_ALLOWED [(GND_20)]" "ALL_ALLOWED" "" "DRC ERROR CLASS/TOP" "[SmdPin] GND (<uTiL>cId5788<uTiL>.9) (265.0 3282.98)" "[ThruPin] GND (<uTiL>cId5788<uTiL>.16) (287.74 3323.2)" list(287.740000 3323.200000) nil)@@@list("eric2_tseng" "2019/01/23 17:33:23" nil "p143000044-pc" "5s-ipcfl-cg.a00r")@@@list("doris_chen" "2019/01/24 12:52:00" nil "p16c000356-pc" "5s-ipcfl-cg.a00r-chk") | list("[Physical] TOP" "61.Pad/Pad Direct Connect" "NOT_ALLOWED [(GND_20)]" "ALL_ALLOWED" "" "DRC ERROR CLASS/TOP" "[SmdPin] GND (<uTiL>cId5788<uTiL>.9) (265.0 3282.98)" "[ThruPin] GND (<uTiL>cId5788<uTiL>.15) (287.74 3243.2)" list(287.740000 3243.200000) nil)@@@list("eric2_tseng" "2019/01/23 17:33:22" nil "p143000044-pc" "5s-ipcfl-cg.a00r")@@@list("doris_chen" "2019/01/24 12:51:45" nil "p16c000356-pc" "5s-ipcfl-cg.a00r-chk") | list("[Physical] TOP" "113.Pad/Pad Direct Connect" "NOT_ALLOWED [(GND_20)]" "ALL_ALLOWED" "" "DRC ERROR CLASS/TOP" "[SmdPin] GND (<uTiL>cId5788<uTiL>.9) (265.0 3282.98)" "[ThruPin] GND (<uTiL>cId5788<uTiL>.18) (332.74 3323.2)" list(332.740000 3323.200000) nil)@@@list("eric2_tseng" "2019/01/23 17:33:24" nil "p143000044-pc" "5s-ipcfl-cg.a00r")@@@list("doris_chen" "2019/01/24 12:52:17" nil "p16c000356-pc" "5s-ipcfl-cg.a00r-chk") | list("[Physical] TOP" "55.Pad/Pad Direct Connect" "NOT_ALLOWED [(GND_20)]" "ALL_ALLOWED" "" "DRC ERROR CLASS/TOP" "[SmdPin] GND (<uTiL>cId5788<uTiL>.9) (265.0 3282.98)" "[ThruPin] GND (<uTiL>cId5788<uTiL>.17) (332.74 3288.2)" list(332.740000 3288.200000) nil)@@@list("eric2_tseng" "2019/01/23 17:33:29" nil "p143000044-pc" "5s-ipcfl-cg.a00r")@@@list("doris_chen" "2019/01/24 12:51:42" nil "p16c000356-pc" "5s-ipcfl-cg.a00r-chk") | list("[Physical] TOP" "199.Pad/Pad Direct Connect" "NOT_ALLOWED [(PWR_20)]" "ALL_ALLOWED" "" "DRC ERROR CLASS/TOP" "[ThruPin] VCORE_+19V (<uTiL>cId5788<uTiL>.20) (335.0 3371.17)" "[SmdPin] VCORE_+19V (<uTiL>cId5788<uTiL>.10) (265.0 3370.17)" list(335.000000 3371.170000) nil)@@@list("eric2_tseng" "2019/01/23 17:33:18" nil "p143000044-pc" "5s-ipcfl-cg.a00r")@@@list("doris_chen" "2019/01/24 12:53:06" nil "p16c000356-pc" "5s-ipcfl-cg.a00r-chk") | list("[Physical] TOP" "123.Pad/Pad Direct Connect" "NOT_ALLOWED [(PWR_20)]" "ALL_ALLOWED" "" "DRC ERROR CLASS/TOP" "[SmdPin] +5VSB (<uTiL>cId2239<uTiL>.1) (602.56 -1990.0)" "[SmdPin] +5VSB (<uTiL>cId712<uTiL>.1) (654.5 -1990.0)" list(654.500000 -1990.000000) nil)@@@list("eric2_tseng" "2019/01/23 17:34:19" nil "p143000044-pc" "5s-ipcfl-cg.a00r")@@@list("doris_chen" "2019/01/24 12:52:22" nil "p16c000356-pc" "5s-ipcfl-cg.a00r-chk") | list("[Physical] TOP" "198.Pad/Pad Direct Connect" "NOT_ALLOWED [(PWR_20)]" "ALL_ALLOWED" "" "DRC ERROR CLASS/TOP" "[SmdPin] VCORE_+19V (<uTiL>cId5789<uTiL>.10) (755.0 3370.17)" "[ThruPin] VCORE_+19V (<uTiL>cId5789<uTiL>.19) (685.0 3371.17)" list(685.000000 3371.170000) nil)@@@list("eric2_tseng" "2019/01/23 17:33:56" nil "p143000044-pc" "5s-ipcfl-cg.a00r")@@@list("doris_chen" "2019/01/24 12:53:05" nil "p16c000356-pc" "5s-ipcfl-cg.a00r-chk") | list("[Physical] TOP" "114.Pad/Pad Direct Connect" "NOT_ALLOWED [(GND_20)]" "ALL_ALLOWED" "" "DRC ERROR CLASS/TOP" "[ThruPin] GND (<uTiL>cId5789<uTiL>.12) (687.74 3323.2)" "[SmdPin] GND (<uTiL>cId5789<uTiL>.9) (755.0 3282.98)" list(687.740000 3323.200000) nil)@@@list("eric2_tseng" "2019/01/23 17:33:26" nil "p143000044-pc" "5s-ipcfl-cg.a00r")@@@list("doris_chen" "2019/01/24 12:52:17" nil "p16c000356-pc" "5s-ipcfl-cg.a00r-chk") | list("[Physical] TOP" "118.Pad/Pad Direct Connect" "NOT_ALLOWED [(GND_20)]" "ALL_ALLOWED" "" "DRC ERROR CLASS/TOP" "[SmdPin] GND (<uTiL>cId5789<uTiL>.9) (755.0 3282.98)" "[ThruPin] GND (<uTiL>cId5789<uTiL>.11) (687.74 3243.2)" list(687.740000 3243.200000) nil)@@@list("eric2_tseng" "2019/01/23 17:33:25" nil "p143000044-pc" "5s-ipcfl-cg.a00r")@@@list("doris_chen" "2019/01/24 12:52:19" nil "p16c000356-pc" "5s-ipcfl-cg.a00r-chk") | list("[Physical] TOP" "115.Pad/Pad Direct Connect" "NOT_ALLOWED [(GND_20)]" "ALL_ALLOWED" "" "DRC ERROR CLASS/TOP" "[ThruPin] GND (<uTiL>cId5789<uTiL>.14) (732.74 3323.2)" "[SmdPin] GND (<uTiL>cId5789<uTiL>.9) (755.0 3282.98)" list(732.740000 3323.200000) nil)@@@list("eric2_tseng" "2019/01/23 17:34:06" nil "p143000044-pc" "5s-ipcfl-cg.a00r")@@@list("doris_chen" "2019/01/24 12:52:18" nil "p16c000356-pc" "5s-ipcfl-cg.a00r-chk") | list("[Physical] TOP" "147.Pad/Pad Direct Connect" "NOT_ALLOWED [(GND_20)]" "ALL_ALLOWED" "" "DRC ERROR CLASS/TOP" "[SmdPin] GND (<uTiL>cId5789<uTiL>.9) (755.0 3282.98)" "[ThruPin] GND (<uTiL>cId5789<uTiL>.13) (732.74 3243.2)" list(732.740000 3243.200000) nil)@@@list("eric2_tseng" "2019/01/23 17:33:56" nil "p143000044-pc" "5s-ipcfl-cg.a00r")@@@list("doris_chen" "2019/01/24 12:52:37" nil "p16c000356-pc" "5s-ipcfl-cg.a00r-chk") | list("[Physical] TOP" "116.Pad/Pad Direct Connect" "NOT_ALLOWED [(GND_20)]" "ALL_ALLOWED" "" "DRC ERROR CLASS/TOP" "[ThruPin] GND (<uTiL>cId5789<uTiL>.16) (777.74 3323.2)" "[SmdPin] GND (<uTiL>cId5789<uTiL>.9) (755.0 3282.98)" list(777.740000 3323.200000) nil)@@@list("eric2_tseng" "2019/01/23 17:33:26" nil "p143000044-pc" "5s-ipcfl-cg.a00r")@@@list("doris_chen" "2019/01/24 12:52:18" nil "p16c000356-pc" "5s-ipcfl-cg.a00r-chk") | list("[Physical] TOP" "117.Pad/Pad Direct Connect" "NOT_ALLOWED [(GND_20)]" "ALL_ALLOWED" "" "DRC ERROR CLASS/TOP" "[ThruPin] GND (<uTiL>cId5789<uTiL>.15) (777.74 3243.2)" "[SmdPin] GND (<uTiL>cId5789<uTiL>.9) (755.0 3282.98)" list(777.740000 3243.200000) nil)@@@list("eric2_tseng" "2019/01/23 17:33:30" nil "p143000044-pc" "5s-ipcfl-cg.a00r")@@@list("doris_chen" "2019/01/24 12:52:19" nil "p16c000356-pc" "5s-ipcfl-cg.a00r-chk") | list("[Physical] TOP" "194.Pad/Pad Direct Connect" "NOT_ALLOWED [(PWR_20)]" "ALL_ALLOWED" "" "DRC ERROR CLASS/TOP" "[SmdPin] CORE_PWM2_SW_S (<uTiL>cId2349<uTiL>.1) (780.0 3050.5)" "[SmdPin] CORE_PWM2_SW_S (<uTiL>cId5777<uTiL>.1) (777.0 3089.05)" list(780.000000 3050.500000) nil)@@@list("eric2_tseng" "2019/01/23 17:33:51" nil "p143000044-pc" "5s-ipcfl-cg.a00r")@@@list("doris_chen" "2019/01/24 12:53:03" nil "p16c000356-pc" "5s-ipcfl-cg.a00r-chk") | list("[Physical] TOP" "125.Pad/Pad Direct Connect" "NOT_ALLOWED [(PWR_20)]" "ALL_ALLOWED" "" "DRC ERROR CLASS/TOP" "[SmdPin] +VCORE (<uTiL>cId2348<uTiL>.1) (780.0 2884.5)" "[SmdPin] +VCORE (<uTiL>cId5777<uTiL>.2) (777.0 2844.95)" list(780.000000 2884.500000) nil)@@@list("eric2_tseng" "2019/01/23 17:33:14" nil "p143000044-pc" "5s-ipcfl-cg.a00r")@@@list("doris_chen" "2019/01/24 12:52:23" nil "p16c000356-pc" "5s-ipcfl-cg.a00r-chk") | list("[Physical] TOP" "148.Pad/Pad Direct Connect" "NOT_ALLOWED [(GND_20)]" "ALL_ALLOWED" "" "DRC ERROR CLASS/TOP" "[SmdPin] GND (<uTiL>cId5789<uTiL>.9) (755.0 3282.98)" "[ThruPin] GND (<uTiL>cId5789<uTiL>.18) (822.74 3323.2)" list(822.740000 3323.200000) nil)@@@list("eric2_tseng" "2019/01/23 17:33:31" nil "p143000044-pc" "5s-ipcfl-cg.a00r")@@@list("doris_chen" "2019/01/24 12:52:38" nil "p16c000356-pc" "5s-ipcfl-cg.a00r-chk") | list("[Physical] TOP" "119.Pad/Pad Direct Connect" "NOT_ALLOWED [(GND_20)]" "ALL_ALLOWED" "" "DRC ERROR CLASS/TOP" "[SmdPin] GND (<uTiL>cId5789<uTiL>.9) (755.0 3282.98)" "[ThruPin] GND (<uTiL>cId5789<uTiL>.17) (822.74 3288.2)" list(822.740000 3288.200000) nil)@@@list("eric2_tseng" "2019/01/23 17:33:25" nil "p143000044-pc" "5s-ipcfl-cg.a00r")@@@list("doris_chen" "2019/01/24 12:52:20" nil "p16c000356-pc" "5s-ipcfl-cg.a00r-chk") | list("[Physical] TOP" "197.Pad/Pad Direct Connect" "NOT_ALLOWED [(PWR_20)]" "ALL_ALLOWED" "" "DRC ERROR CLASS/TOP" "[ThruPin] VCORE_+19V (<uTiL>cId5789<uTiL>.20) (825.0 3371.17)" "[SmdPin] VCORE_+19V (<uTiL>cId5789<uTiL>.10) (755.0 3370.17)" list(825.000000 3371.170000) nil)@@@list("eric2_tseng" "2019/01/23 17:33:30" nil "p143000044-pc" "5s-ipcfl-cg.a00r")@@@list("doris_chen" "2019/01/24 12:53:05" nil "p16c000356-pc" "5s-ipcfl-cg.a00r-chk") | list("[Physical] TOP" "195.Pad/Pad Direct Connect" "NOT_ALLOWED [(PWR_20)]" "ALL_ALLOWED" "" "DRC ERROR CLASS/TOP" "[ThruPin] VCORE_+19V (<uTiL>cId5790<uTiL>.19) (1392.0 3343.17)" "[SmdPin] VCORE_+19V (<uTiL>cId5790<uTiL>.10) (1462.0 3342.17)" list(1392.000000 3343.170000) nil)@@@list("eric2_tseng" "2019/01/23 17:33:57" nil "p143000044-pc" "5s-ipcfl-cg.a00r")@@@list("doris_chen" "2019/01/24 12:53:04" nil "p16c000356-pc" "5s-ipcfl-cg.a00r-chk") | list("[Physical] TOP" "155.Pad/Pad Direct Connect" "NOT_ALLOWED [(GND_20)]" "ALL_ALLOWED" "" "DRC ERROR CLASS/TOP" "[ThruPin] GND (<uTiL>cId5790<uTiL>.12) (1394.74 3295.2)" "[SmdPin] GND (<uTiL>cId5790<uTiL>.9) (1462.0 3254.98)" list(1394.740000 3295.200000) nil)@@@list("eric2_tseng" "2019/01/23 17:33:38" nil "p143000044-pc" "5s-ipcfl-cg.a00r")@@@list("doris_chen" "2019/01/24 12:52:42" nil "p16c000356-pc" "5s-ipcfl-cg.a00r-chk") | list("[Physical] TOP" "154.Pad/Pad Direct Connect" "NOT_ALLOWED [(GND_20)]" "ALL_ALLOWED" "" "DRC ERROR CLASS/TOP" "[ThruPin] GND (<uTiL>cId5790<uTiL>.11) (1394.74 3215.2)" "[SmdPin] GND (<uTiL>cId5790<uTiL>.9) (1462.0 3254.98)" list(1394.740000 3215.200000) nil)@@@list("eric2_tseng" "2019/01/23 17:34:06" nil "p143000044-pc" "5s-ipcfl-cg.a00r")@@@list("doris_chen" "2019/01/24 12:52:42" nil "p16c000356-pc" "5s-ipcfl-cg.a00r-chk") | list("[Physical] TOP" "156.Pad/Pad Direct Connect" "NOT_ALLOWED [(GND_20)]" "ALL_ALLOWED" "" "DRC ERROR CLASS/TOP" "[SmdPin] GND (<uTiL>cId5790<uTiL>.9) (1462.0 3254.98)" "[ThruPin] GND (<uTiL>cId5790<uTiL>.14) (1439.74 3295.2)" list(1439.740000 3295.200000) nil)@@@list("eric2_tseng" "2019/01/23 17:33:32" nil "p143000044-pc" "5s-ipcfl-cg.a00r")@@@list("doris_chen" "2019/01/24 12:52:43" nil "p16c000356-pc" "5s-ipcfl-cg.a00r-chk") | list("[Physical] TOP" "149.Pad/Pad Direct Connect" "NOT_ALLOWED [(GND_20)]" "ALL_ALLOWED" "" "DRC ERROR CLASS/TOP" "[ThruPin] GND (<uTiL>cId5790<uTiL>.13) (1439.74 3215.2)" "[SmdPin] GND (<uTiL>cId5790<uTiL>.9) (1462.0 3254.98)" list(1439.740000 3215.200000) nil)@@@list("eric2_tseng" "2019/01/23 17:33:31" nil "p143000044-pc" "5s-ipcfl-cg.a00r")@@@list("doris_chen" "2019/01/24 12:52:39" nil "p16c000356-pc" "5s-ipcfl-cg.a00r-chk") | list("[Physical] TOP" "151.Pad/Pad Direct Connect" "NOT_ALLOWED [(GND_20)]" "ALL_ALLOWED" "" "DRC ERROR CLASS/TOP" "[ThruPin] GND (<uTiL>cId5790<uTiL>.16) (1484.74 3295.2)" "[SmdPin] GND (<uTiL>cId5790<uTiL>.9) (1462.0 3254.98)" list(1484.740000 3295.200000) nil)@@@list("eric2_tseng" "2019/01/23 17:34:07" nil "p143000044-pc" "5s-ipcfl-cg.a00r")@@@list("doris_chen" "2019/01/24 12:52:40" nil "p16c000356-pc" "5s-ipcfl-cg.a00r-chk") | list("[Physical] TOP" "150.Pad/Pad Direct Connect" "NOT_ALLOWED [(GND_20)]" "ALL_ALLOWED" "" "DRC ERROR CLASS/TOP" "[ThruPin] GND (<uTiL>cId5790<uTiL>.15) (1484.74 3215.2)" "[SmdPin] GND (<uTiL>cId5790<uTiL>.9) (1462.0 3254.98)" list(1484.740000 3215.200000) nil)@@@list("eric2_tseng" "2019/01/23 17:33:39" nil "p143000044-pc" "5s-ipcfl-cg.a00r")@@@list("doris_chen" "2019/01/24 12:52:39" nil "p16c000356-pc" "5s-ipcfl-cg.a00r-chk") | list("[Physical] TOP" "163.Pad/Pad Direct Connect" "NOT_ALLOWED [(PWR_20)]" "ALL_ALLOWED" "" "DRC ERROR CLASS/TOP" "[SmdPin] +VCORE (<uTiL>cId5778<uTiL>.2) (1500.0 2844.95)" "[SmdPin] +VCORE (<uTiL>cId2350<uTiL>.1) (1490.0 2879.5)" list(1490.000000 2879.500000) nil)@@@list("eric2_tseng" "2019/01/23 17:34:19" nil "p143000044-pc" "5s-ipcfl-cg.a00r")@@@list("doris_chen" "2019/01/24 12:52:46" nil "p16c000356-pc" "5s-ipcfl-cg.a00r-chk") | list("[Physical] TOP" "126.Pad/Pad Direct Connect" "NOT_ALLOWED [(PWR_20)]" "ALL_ALLOWED" "" "DRC ERROR CLASS/TOP" "[SmdPin] CORE_PWM1_SW_S (<uTiL>cId2351<uTiL>.1) (1495.0 3050.5)" "[SmdPin] CORE_PWM1_SW_S (<uTiL>cId5778<uTiL>.1) (1500.0 3089.05)" list(1495.000000 3050.500000) nil)@@@list("eric2_tseng" "2019/01/23 17:33:59" nil "p143000044-pc" "5s-ipcfl-cg.a00r")@@@list("doris_chen" "2019/01/24 12:52:24" nil "p16c000356-pc" "5s-ipcfl-cg.a00r-chk") | list("[Physical] TOP" "153.Pad/Pad Direct Connect" "NOT_ALLOWED [(GND_20)]" "ALL_ALLOWED" "" "DRC ERROR CLASS/TOP" "[ThruPin] GND (<uTiL>cId5790<uTiL>.18) (1529.74 3295.2)" "[SmdPin] GND (<uTiL>cId5790<uTiL>.9) (1462.0 3254.98)" list(1529.740000 3295.200000) nil)@@@list("eric2_tseng" "2019/01/23 17:33:40" nil "p143000044-pc" "5s-ipcfl-cg.a00r")@@@list("doris_chen" "2019/01/24 12:52:41" nil "p16c000356-pc" "5s-ipcfl-cg.a00r-chk") | list("[Physical] TOP" "152.Pad/Pad Direct Connect" "NOT_ALLOWED [(GND_20)]" "ALL_ALLOWED" "" "DRC ERROR CLASS/TOP" "[ThruPin] GND (<uTiL>cId5790<uTiL>.17) (1529.74 3260.2)" "[SmdPin] GND (<uTiL>cId5790<uTiL>.9) (1462.0 3254.98)" list(1529.740000 3260.200000) nil)@@@list("eric2_tseng" "2019/01/23 17:33:32" nil "p143000044-pc" "5s-ipcfl-cg.a00r")@@@list("doris_chen" "2019/01/24 12:52:40" nil "p16c000356-pc" "5s-ipcfl-cg.a00r-chk") | list("[Physical] TOP" "196.Pad/Pad Direct Connect" "NOT_ALLOWED [(PWR_20)]" "ALL_ALLOWED" "" "DRC ERROR CLASS/TOP" "[SmdPin] VCORE_+19V (<uTiL>cId5790<uTiL>.10) (1462.0 3342.17)" "[ThruPin] VCORE_+19V (<uTiL>cId5790<uTiL>.20) (1532.0 3343.17)" list(1532.000000 3343.170000) nil)@@@list("eric2_tseng" "2019/01/23 17:33:39" nil "p143000044-pc" "5s-ipcfl-cg.a00r")@@@list("doris_chen" "2019/01/24 12:53:04" nil "p16c000356-pc" "5s-ipcfl-cg.a00r-chk") | list("[Physical] TOP" "128.Pad/Pad Direct Connect" "NOT_ALLOWED [(PWR_10)]" "ALL_ALLOWED" "" "DRC ERROR CLASS/TOP" "[SmdPin] GT_PWM1_SW_S (<uTiL>cId5631<uTiL>.9) (1894.0 3114.83)" "[ThruPin] GT_PWM1_SW_S (<uTiL>cId5631<uTiL>.13) (1827.83 3074.36)" list(1827.830000 3074.360000) nil)@@@list("eric2_tseng" "2019/01/23 17:33:47" nil "p143000044-pc" "5s-ipcfl-cg.a00r")@@@list("doris_chen" "2019/01/24 12:52:25" nil "p16c000356-pc" "5s-ipcfl-cg.a00r-chk") | list("[Physical] TOP" "129.Pad/Pad Direct Connect" "NOT_ALLOWED [(PWR_10)]" "ALL_ALLOWED" "" "DRC ERROR CLASS/TOP" "[SmdPin] GT_PWM1_SW_S (<uTiL>cId5631<uTiL>.9) (1894.0 3114.83)" "[ThruPin] GT_PWM1_SW_S (<uTiL>cId5631<uTiL>.17) (1827.9 3155.27)" list(1827.900000 3155.270000) nil)@@@list("eric2_tseng" "2019/01/23 17:34:12" nil "p143000044-pc" "5s-ipcfl-cg.a00r")@@@list("doris_chen" "2019/01/24 12:52:25" nil "p16c000356-pc" "5s-ipcfl-cg.a00r-chk") | list("[Physical] TOP" "52.Pad/Pad Direct Connect" "NOT_ALLOWED [(PWR_10)]" "ALL_ALLOWED" "" "DRC ERROR CLASS/TOP" "[SmdPin] GT_PWM1_SW_S (<uTiL>cId5631<uTiL>.9) (1894.0 3114.83)" "[ThruPin] GT_PWM1_SW_S (<uTiL>cId5631<uTiL>.12) (1871.77 3074.36)" list(1871.770000 3074.360000) nil)@@@list("eric2_tseng" "2019/01/23 17:34:11" nil "p143000044-pc" "5s-ipcfl-cg.a00r")@@@list("doris_chen" "2019/01/24 12:51:40" nil "p16c000356-pc" "5s-ipcfl-cg.a00r-chk") | list("[Physical] TOP" "67.Pad/Pad Direct Connect" "NOT_ALLOWED [(PWR_10)]" "ALL_ALLOWED" "" "DRC ERROR CLASS/TOP" "[SmdPin] GT_PWM1_SW_S (<uTiL>cId5631<uTiL>.9) (1894.0 3114.83)" "[ThruPin] GT_PWM1_SW_S (<uTiL>cId5631<uTiL>.16) (1871.83 3155.27)" list(1871.830000 3155.270000) nil)@@@list("eric2_tseng" "2019/01/23 17:33:47" nil "p143000044-pc" "5s-ipcfl-cg.a00r")@@@list("doris_chen" "2019/01/24 12:51:51" nil "p16c000356-pc" "5s-ipcfl-cg.a00r-chk") | list("[Physical] TOP" "66.Pad/Pad Direct Connect" "NOT_ALLOWED [(PWR_10)]" "ALL_ALLOWED" "" "DRC ERROR CLASS/TOP" "[SmdPin] GT_PWM1_SW_S (<uTiL>cId5631<uTiL>.9) (1894.0 3114.83)" "[ThruPin] GT_PWM1_SW_S (<uTiL>cId5631<uTiL>.11) (1916.1 3074.36)" list(1916.100000 3074.360000) nil)@@@list("eric2_tseng" "2019/01/23 17:33:50" nil "p143000044-pc" "5s-ipcfl-cg.a00r")@@@list("doris_chen" "2019/01/24 12:51:51" nil "p16c000356-pc" "5s-ipcfl-cg.a00r-chk") | list("[Physical] TOP" "53.Pad/Pad Direct Connect" "NOT_ALLOWED [(PWR_10)]" "ALL_ALLOWED" "" "DRC ERROR CLASS/TOP" "[SmdPin] GT_PWM1_SW_S (<uTiL>cId5631<uTiL>.9) (1894.0 3114.83)" "[ThruPin] GT_PWM1_SW_S (<uTiL>cId5631<uTiL>.15) (1916.17 3155.27)" list(1916.170000 3155.270000) nil)@@@list("eric2_tseng" "2019/01/23 17:33:48" nil "p143000044-pc" "5s-ipcfl-cg.a00r")@@@list("doris_chen" "2019/01/24 12:51:41" nil "p16c000356-pc" "5s-ipcfl-cg.a00r-chk") | list("[Physical] TOP" "127.Pad/Pad Direct Connect" "NOT_ALLOWED [(PWR_10)]" "ALL_ALLOWED" "" "DRC ERROR CLASS/TOP" "[SmdPin] GT_PWM1_SW_S (<uTiL>cId5631<uTiL>.9) (1894.0 3114.83)" "[ThruPin] GT_PWM1_SW_S (<uTiL>cId5631<uTiL>.10) (1960.43 3074.36)" list(1960.430000 3074.360000) nil)@@@list("eric2_tseng" "2019/01/23 17:33:51" nil "p143000044-pc" "5s-ipcfl-cg.a00r")@@@list("doris_chen" "2019/01/24 12:52:24" nil "p16c000356-pc" "5s-ipcfl-cg.a00r-chk") | list("[Physical] TOP" "92.Pad/Pad Direct Connect" "NOT_ALLOWED [(PWR_10)]" "ALL_ALLOWED" "" "DRC ERROR CLASS/TOP" "[SmdPin] GT_PWM1_SW_S (<uTiL>cId5631<uTiL>.9) (1894.0 3114.83)" "[ThruPin] GT_PWM1_SW_S (<uTiL>cId5631<uTiL>.14) (1960.5 3155.27)" list(1960.500000 3155.270000) nil)@@@list("eric2_tseng" "2019/01/23 17:33:50" nil "p143000044-pc" "5s-ipcfl-cg.a00r")@@@list("doris_chen" "2019/01/24 12:52:05" nil "p16c000356-pc" "5s-ipcfl-cg.a00r-chk") | list("[Physical] TOP" "90.Pad/Pad Direct Connect" "NOT_ALLOWED [(PWR_10)]" "ALL_ALLOWED" "" "DRC ERROR CLASS/TOP" "[SmdPin] GT_PWM1_SW_S (<uTiL>cId2662<uTiL>.1) (2112.67 3151.43)" "[SmdPin] GT_PWM1_SW_S (<uTiL>cId2345<uTiL>.1) (2146.5 3146.0)" list(2146.500000 3146.000000) nil)@@@list("eric2_tseng" "2019/01/23 17:34:00" nil "p143000044-pc" "5s-ipcfl-cg.a00r")@@@list("doris_chen" "2019/01/24 12:52:04" nil "p16c000356-pc" "5s-ipcfl-cg.a00r-chk") | list("[Physical] TOP" "101.Pad/Pad Direct Connect" "NOT_ALLOWED [(PWR_20)]" "ALL_ALLOWED" "" "DRC ERROR CLASS/TOP" "[SmdPin] +VCCGT (<uTiL>cId2662<uTiL>.2) (2356.77 3151.43)" "[SmdPin] +VCCGT (<uTiL>cId2344<uTiL>.1) (2317.5 3146.0)" list(2317.500000 3146.000000) nil)@@@list("eric2_tseng" "2019/01/23 17:34:20" nil "p143000044-pc" "5s-ipcfl-cg.a00r")@@@list("doris_chen" "2019/01/24 12:52:10" nil "p16c000356-pc" "5s-ipcfl-cg.a00r-chk") | list("[Physical] TOP" "145.Pad/Pad Direct Connect" "NOT_ALLOWED [(PWR_20)]" "ALL_ALLOWED" "" "DRC ERROR CLASS/TOP" "[SmdPin] +1P2V_DUAL (<uTiL>cId2352<uTiL>.1) (2432.43 -1976.22)" "[ThruPin] +1P2V_DUAL (<uTiL>cId3004<uTiL>.1) (2432.14 -1993.02)" list(2432.430000 -1976.220000) nil)@@@list("eric2_tseng" "2019/01/23 17:33:19" nil "p143000044-pc" "5s-ipcfl-cg.a00r")@@@list("doris_chen" "2019/01/24 12:52:36" nil "p16c000356-pc" "5s-ipcfl-cg.a00r-chk") | list("[Physical] TOP" "121.Pad/Pad Direct Connect" "NOT_ALLOWED [(PWR_20)]" "ALL_ALLOWED" "" "DRC ERROR CLASS/TOP" "[SmdPin] +ADP_19V (<uTiL>cId322<uTiL>.2) (2902.63 3189.0)" "[SmdPin] +ADP_19V (<uTiL>cId719<uTiL>.1) (2902.0 3124.5)" list(2902.000000 3124.500000) nil)@@@list("eric2_tseng" "2019/01/23 17:34:15" nil "p143000044-pc" "5s-ipcfl-cg.a00r")@@@list("doris_chen" "2019/01/24 12:52:21" nil "p16c000356-pc" "5s-ipcfl-cg.a00r-chk") | list("[Physical] TOP" "48.Pad/Pad Direct Connect" "NOT_ALLOWED [(PWR_20)]" "ALL_ALLOWED" "" "DRC ERROR CLASS/TOP" "[SmdPin] +19VA_PR61365_R (<uTiL>cId719<uTiL>.2) (2902.0 3083.5)" "[SmdPin] +19VA_PR61365_R (<uTiL>cId288<uTiL>.2) (2902.0 3077.5)" list(2902.000000 3077.500000) nil)@@@list("eric2_tseng" "2019/01/23 17:34:09" nil "p143000044-pc" "5s-ipcfl-cg.a00r")@@@list("doris_chen" "2019/01/24 12:51:38" nil "p16c000356-pc" "5s-ipcfl-cg.a00r-chk") | list("[Physical] TOP" "47.Pad/Pad Direct Connect" "NOT_ALLOWED [(PWR_10)]" "ALL_ALLOWED" "" "DRC ERROR CLASS/TOP" "[SmdPin] GT_PWM2_SW_S (<uTiL>cId4450<uTiL>.9) (2984.53 1503.0)" "[ThruPin] GT_PWM2_SW_S (<uTiL>cId4450<uTiL>.13) (2944.06 1569.17)" list(2944.060000 1569.170000) nil)@@@list("eric2_tseng" "2019/01/23 17:34:12" nil "p143000044-pc" "5s-ipcfl-cg.a00r")@@@list("doris_chen" "2019/01/24 12:51:37" nil "p16c000356-pc" "5s-ipcfl-cg.a00r-chk") | list("[Physical] TOP" "46.Pad/Pad Direct Connect" "NOT_ALLOWED [(PWR_10)]" "ALL_ALLOWED" "" "DRC ERROR CLASS/TOP" "[SmdPin] GT_PWM2_SW_S (<uTiL>cId4450<uTiL>.9) (2984.53 1503.0)" "[ThruPin] GT_PWM2_SW_S (<uTiL>cId4450<uTiL>.12) (2944.06 1525.23)" list(2944.060000 1525.230000) nil)@@@list("eric2_tseng" "2019/01/23 17:33:11" nil "p143000044-pc" "5s-ipcfl-cg.a00r")@@@list("doris_chen" "2019/01/24 12:51:37" nil "p16c000356-pc" "5s-ipcfl-cg.a00r-chk") | list("[Physical] TOP" "68.Pad/Pad Direct Connect" "NOT_ALLOWED [(PWR_10)]" "ALL_ALLOWED" "" "DRC ERROR CLASS/TOP" "[SmdPin] GT_PWM2_SW_S (<uTiL>cId4450<uTiL>.9) (2984.53 1503.0)" "[ThruPin] GT_PWM2_SW_S (<uTiL>cId4450<uTiL>.11) (2944.06 1480.9)" list(2944.060000 1480.900000) nil)@@@list("eric2_tseng" "2019/01/23 17:33:14" nil "p143000044-pc" "5s-ipcfl-cg.a00r")@@@list("doris_chen" "2019/01/24 12:51:52" nil "p16c000356-pc" "5s-ipcfl-cg.a00r-chk") | list("[Physical] TOP" "177.Pad/Pad Direct Connect" "NOT_ALLOWED [(PWR_10)]" "ALL_ALLOWED" "" "DRC ERROR CLASS/TOP" "[SmdPin] GT_PWM2_SW_S (<uTiL>cId4450<uTiL>.9) (2984.53 1503.0)" "[ThruPin] GT_PWM2_SW_S (<uTiL>cId4450<uTiL>.10) (2944.06 1436.57)" list(2944.060000 1436.570000) nil)@@@list("eric2_tseng" "2019/01/23 17:33:42" nil "p143000044-pc" "5s-ipcfl-cg.a00r")@@@list("doris_chen" "2019/01/24 12:52:54" nil "p16c000356-pc" "5s-ipcfl-cg.a00r-chk") | list("[Physical] TOP" "57.Pad/Pad Direct Connect" "NOT_ALLOWED [(PWR_20)]" "ALL_ALLOWED" "" "DRC ERROR CLASS/TOP" "[SmdPin] +19VA (<uTiL>cId729<uTiL>.1) (2982.0 3124.5)" "[SmdPin] +19VA (<uTiL>cId322<uTiL>.1) (2981.37 3189.0)" list(2982.000000 3124.500000) nil)@@@list("eric2_tseng" "2019/01/23 17:33:58" nil "p143000044-pc" "5s-ipcfl-cg.a00r")@@@list("doris_chen" "2019/01/24 12:51:43" nil "p16c000356-pc" "5s-ipcfl-cg.a00r-chk") | list("[Physical] TOP" "165.Pad/Pad Direct Connect" "NOT_ALLOWED [(PWR_20)]" "ALL_ALLOWED" "" "DRC ERROR CLASS/TOP" "[SmdPin] +19VA_IN_PR61366_R (<uTiL>cId729<uTiL>.2) (2982.0 3083.5)" "[SmdPin] +19VA_IN_PR61366_R (<uTiL>cId1565<uTiL>.2) (2982.0 3077.5)" list(2982.000000 3077.500000) nil)@@@list("eric2_tseng" "2019/01/23 17:34:17" nil "p143000044-pc" "5s-ipcfl-cg.a00r")@@@list("doris_chen" "2019/01/24 12:52:48" nil "p16c000356-pc" "5s-ipcfl-cg.a00r-chk") | list("[Physical] TOP" "64.Pad/Pad Direct Connect" "NOT_ALLOWED [(PWR_10)]" "ALL_ALLOWED" "" "DRC ERROR CLASS/TOP" "[SmdPin] GT_PWM2_SW_S (<uTiL>cId2661<uTiL>.1) (3002.13 1683.13)" "[SmdPin] GT_PWM2_SW_S (<uTiL>cId2343<uTiL>.1) (3003.0 1721.5)" list(3003.000000 1721.500000) nil)@@@list("eric2_tseng" "2019/01/23 17:34:00" nil "p143000044-pc" "5s-ipcfl-cg.a00r")@@@list("doris_chen" "2019/01/24 12:51:50" nil "p16c000356-pc" "5s-ipcfl-cg.a00r-chk") | list("[Physical] TOP" "175.Pad/Pad Direct Connect" "NOT_ALLOWED [(PWR_20)]" "ALL_ALLOWED" "" "DRC ERROR CLASS/TOP" "[SmdPin] +VCCGT (<uTiL>cId2342<uTiL>.1) (3003.13 1893.68)" "[SmdPin] +VCCGT (<uTiL>cId2661<uTiL>.2) (3002.13 1927.23)" list(3003.130000 1893.680000) nil)@@@list("eric2_tseng" "2019/01/23 17:33:52" nil "p143000044-pc" "5s-ipcfl-cg.a00r")@@@list("doris_chen" "2019/01/24 12:52:53" nil "p16c000356-pc" "5s-ipcfl-cg.a00r-chk") | list("[Physical] TOP" "49.Pad/Pad Direct Connect" "NOT_ALLOWED [(PWR_10)]" "ALL_ALLOWED" "" "DRC ERROR CLASS/TOP" "[SmdPin] GT_PWM2_SW_S (<uTiL>cId4450<uTiL>.9) (2984.53 1503.0)" "[ThruPin] GT_PWM2_SW_S (<uTiL>cId4450<uTiL>.17) (3024.97 1569.1)" list(3024.970000 1569.100000) nil)@@@list("eric2_tseng" "2019/01/23 17:34:13" nil "p143000044-pc" "5s-ipcfl-cg.a00r")@@@list("doris_chen" "2019/01/24 12:51:38" nil "p16c000356-pc" "5s-ipcfl-cg.a00r-chk") | list("[Physical] TOP" "130.Pad/Pad Direct Connect" "NOT_ALLOWED [(PWR_10)]" "ALL_ALLOWED" "" "DRC ERROR CLASS/TOP" "[SmdPin] GT_PWM2_SW_S (<uTiL>cId4450<uTiL>.9) (2984.53 1503.0)" "[ThruPin] GT_PWM2_SW_S (<uTiL>cId4450<uTiL>.16) (3024.97 1525.17)" list(3024.970000 1525.170000) nil)@@@list("eric2_tseng" "2019/01/23 17:34:01" nil "p143000044-pc" "5s-ipcfl-cg.a00r")@@@list("doris_chen" "2019/01/24 12:52:26" nil "p16c000356-pc" "5s-ipcfl-cg.a00r-chk") | list("[Physical] TOP" "178.Pad/Pad Direct Connect" "NOT_ALLOWED [(PWR_10)]" "ALL_ALLOWED" "" "DRC ERROR CLASS/TOP" "[SmdPin] GT_PWM2_SW_S (<uTiL>cId4450<uTiL>.9) (2984.53 1503.0)" "[ThruPin] GT_PWM2_SW_S (<uTiL>cId4450<uTiL>.15) (3024.97 1480.83)" list(3024.970000 1480.830000) nil)@@@list("eric2_tseng" "2019/01/23 17:33:15" nil "p143000044-pc" "5s-ipcfl-cg.a00r")@@@list("doris_chen" "2019/01/24 12:52:54" nil "p16c000356-pc" "5s-ipcfl-cg.a00r-chk") | list("[Physical] TOP" "69.Pad/Pad Direct Connect" "NOT_ALLOWED [(PWR_10)]" "ALL_ALLOWED" "" "DRC ERROR CLASS/TOP" "[SmdPin] GT_PWM2_SW_S (<uTiL>cId4450<uTiL>.9) (2984.53 1503.0)" "[ThruPin] GT_PWM2_SW_S (<uTiL>cId4450<uTiL>.14) (3024.97 1436.5)" list(3024.970000 1436.500000) nil)@@@list("eric2_tseng" "2019/01/23 17:33:43" nil "p143000044-pc" "5s-ipcfl-cg.a00r")@@@list("doris_chen" "2019/01/24 12:51:52" nil "p16c000356-pc" "5s-ipcfl-cg.a00r-chk")
